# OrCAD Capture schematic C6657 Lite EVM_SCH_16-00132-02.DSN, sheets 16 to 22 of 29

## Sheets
16 PAGE16 : DSP_EMIF & JTAG: size C; title: DSP EMIF & JTAG
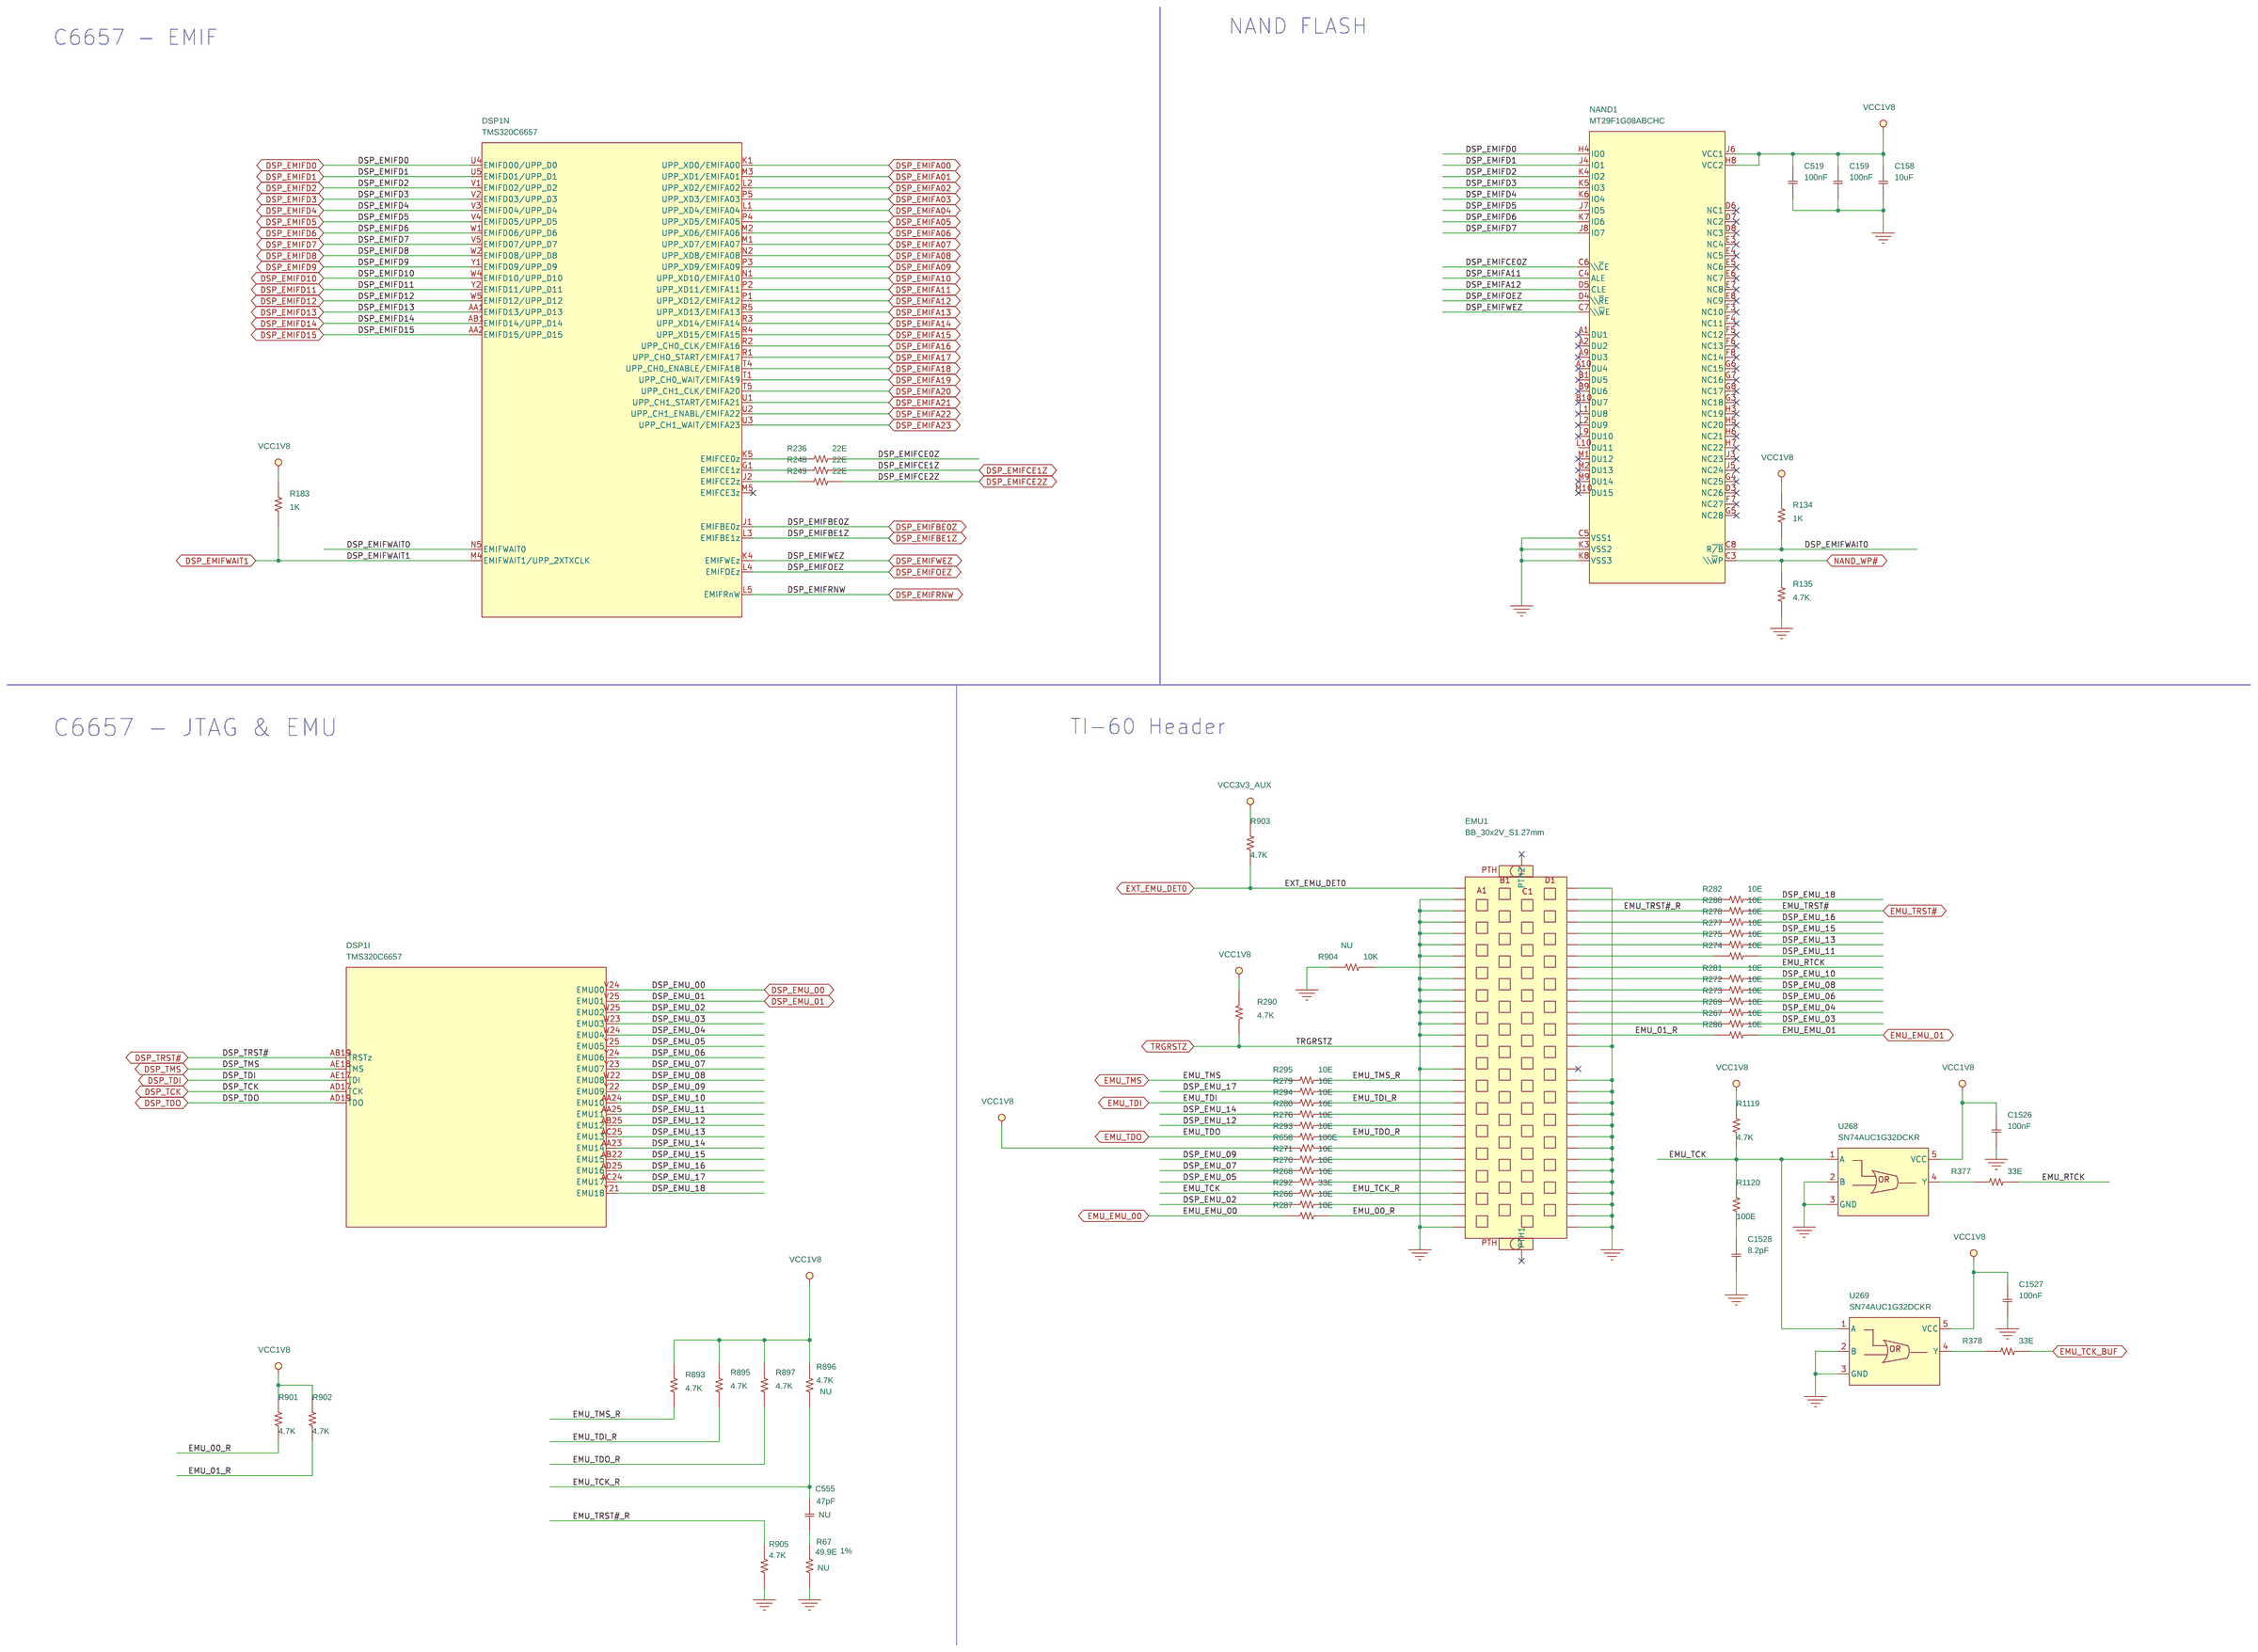
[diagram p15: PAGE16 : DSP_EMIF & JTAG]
17 PAGE29 : REVISON HISTORY: size C; title: REVISION HISTORY
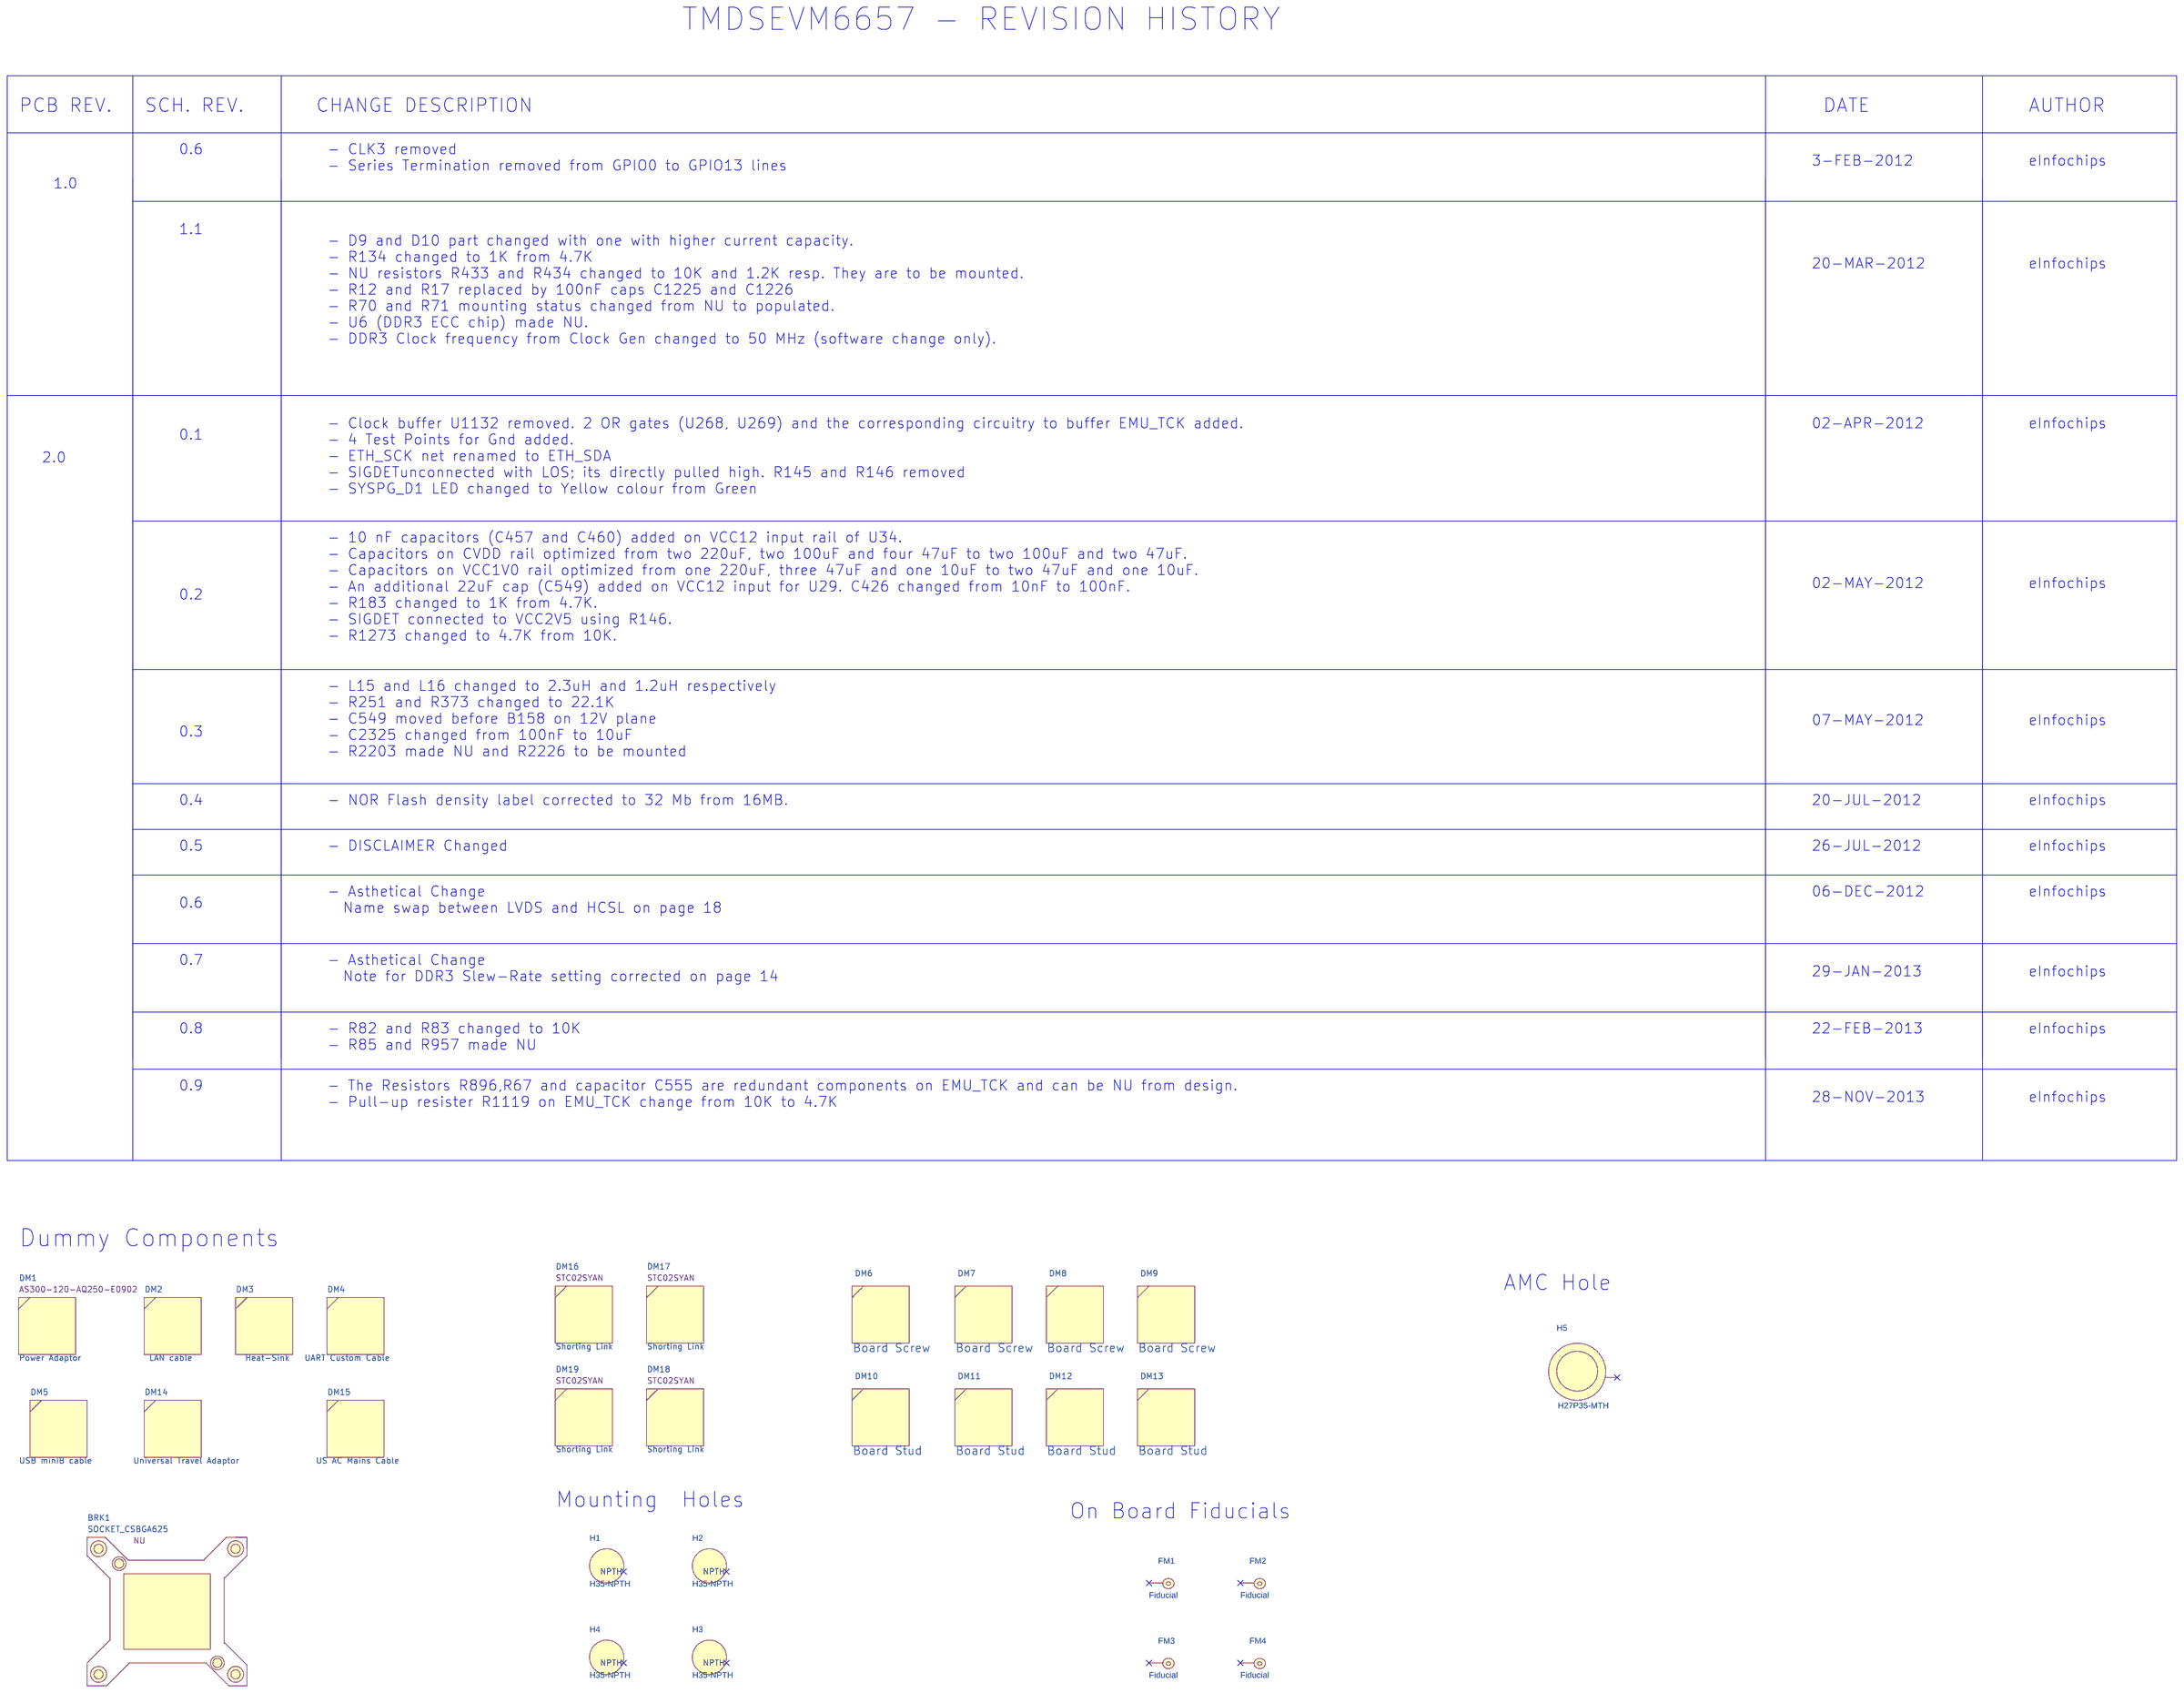
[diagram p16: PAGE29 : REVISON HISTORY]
18 PAGE05 : POWER CONSUMPTION: title: POWER CONSUMPTION
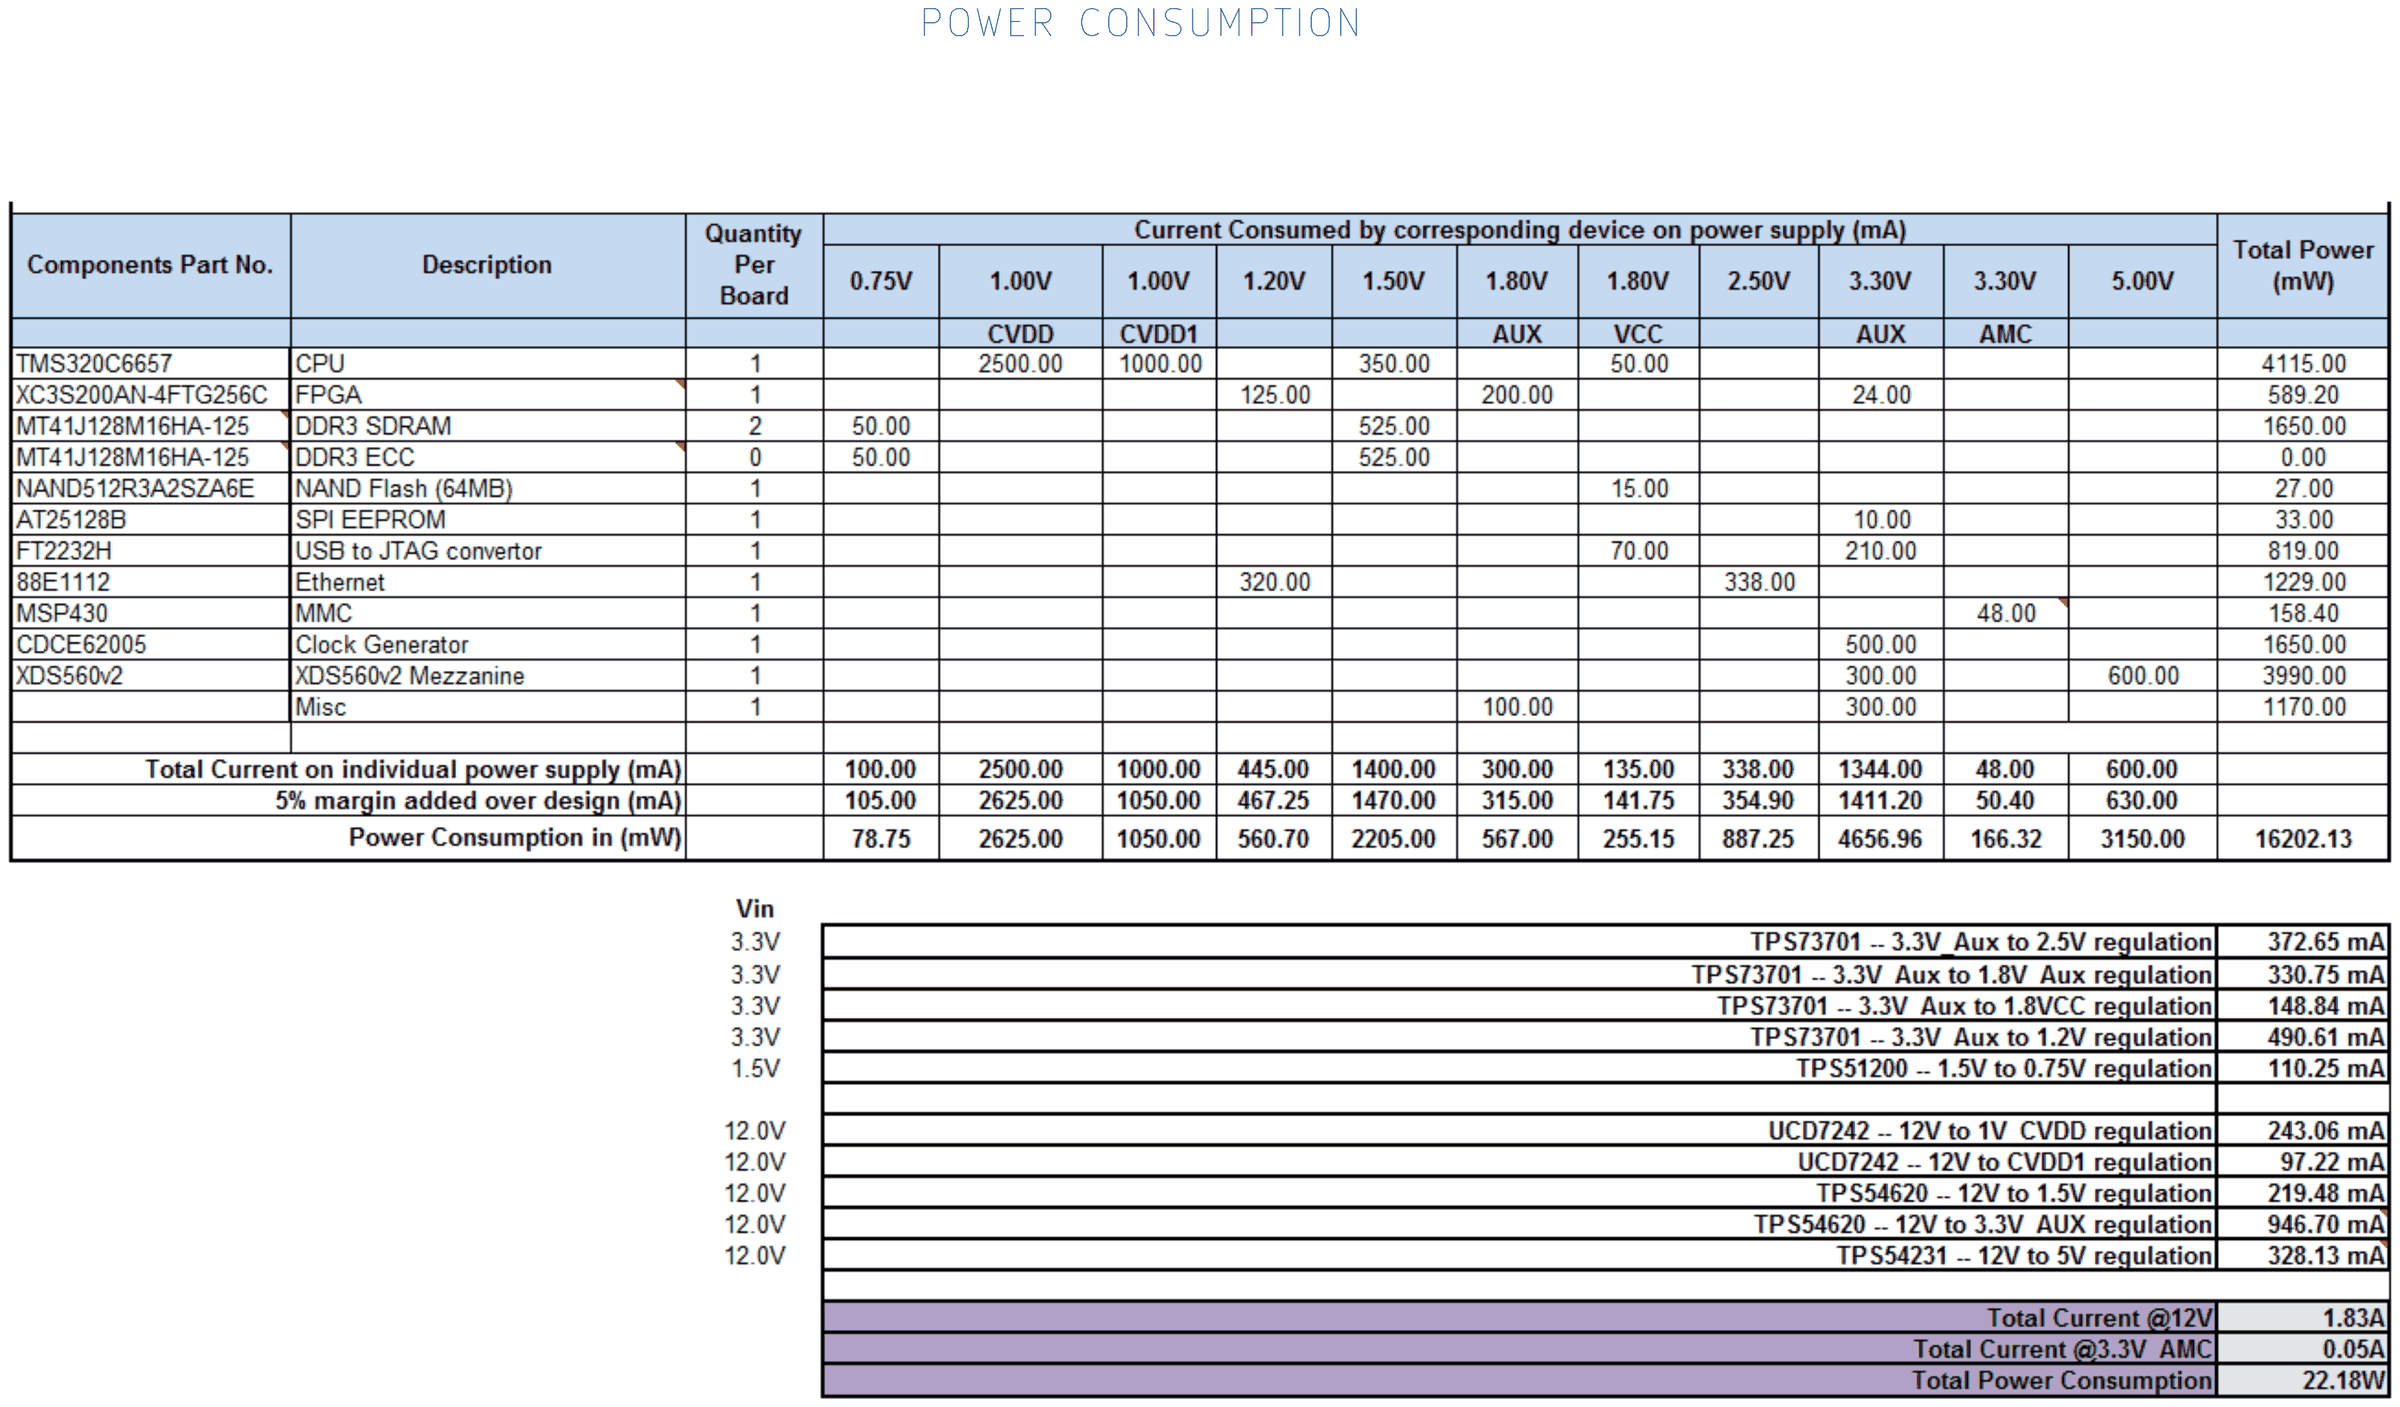
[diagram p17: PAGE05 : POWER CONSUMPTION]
19 PAGE21 : GIGABIT ETHERNET: size C; title: GIGABIT ETHERNET
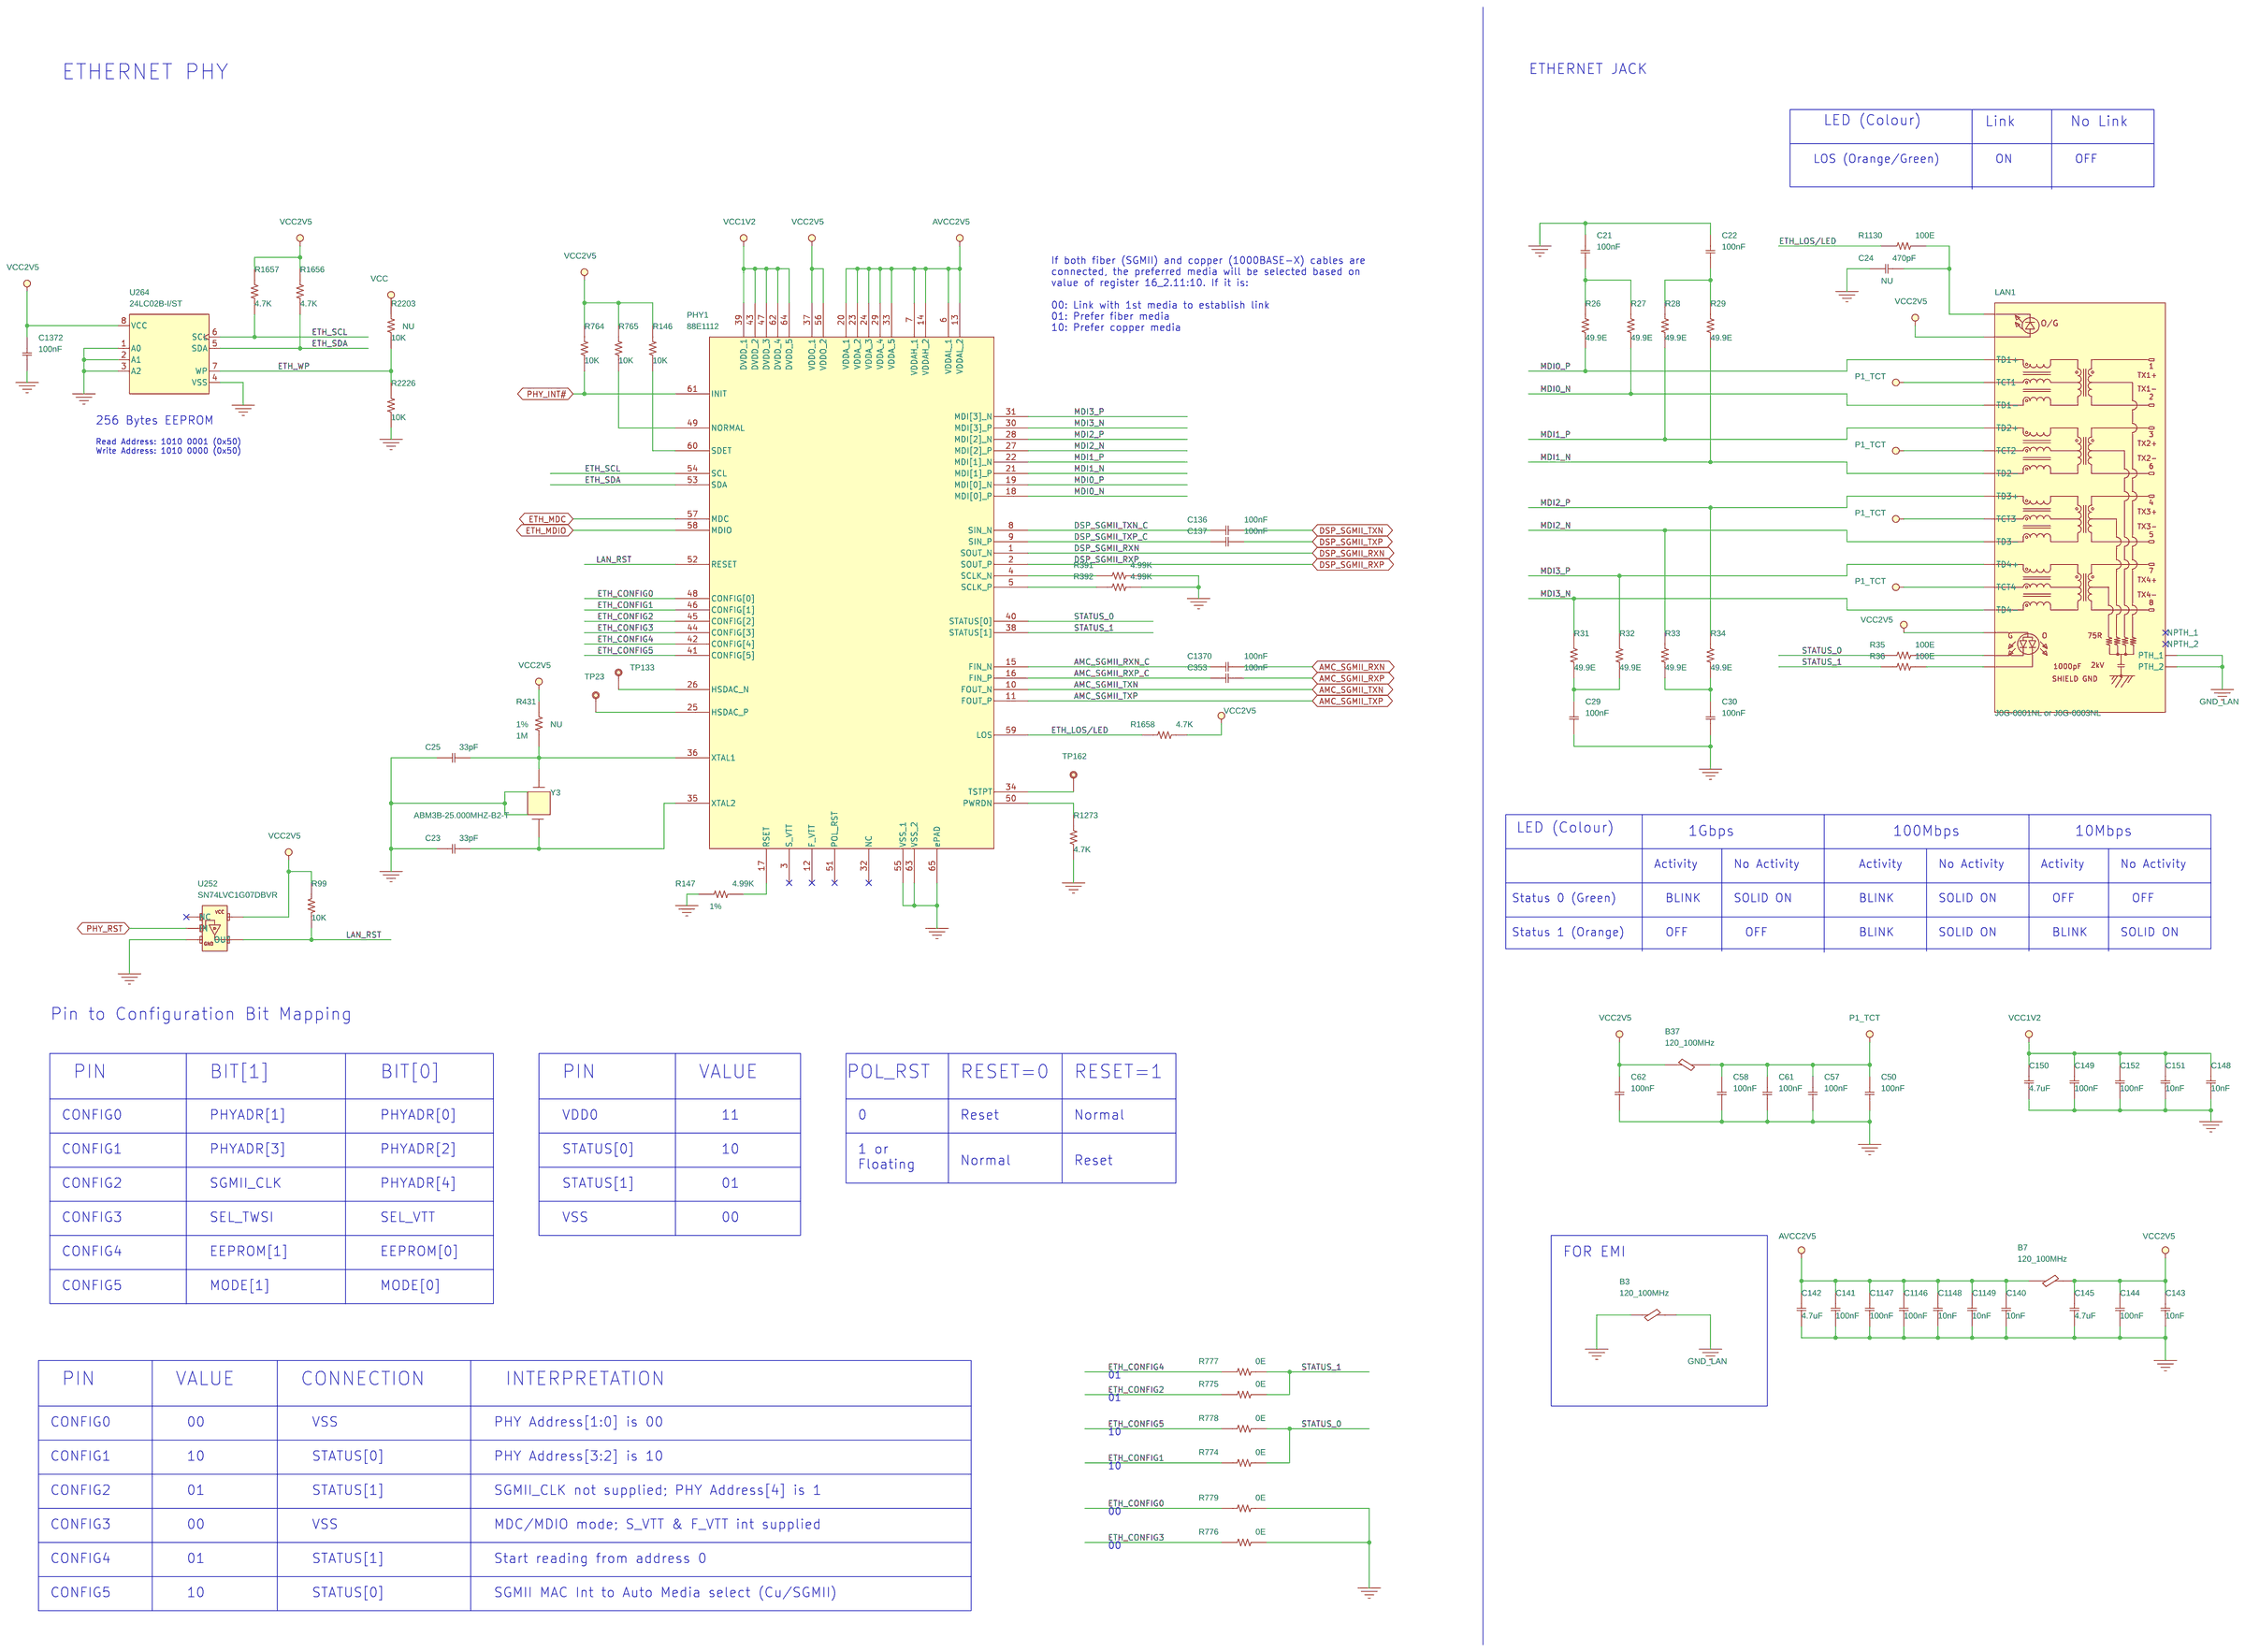
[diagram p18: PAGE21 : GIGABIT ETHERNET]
20 PAGE19 : CLOCK_GENERATION: size C; title: CLOCK GENRATION
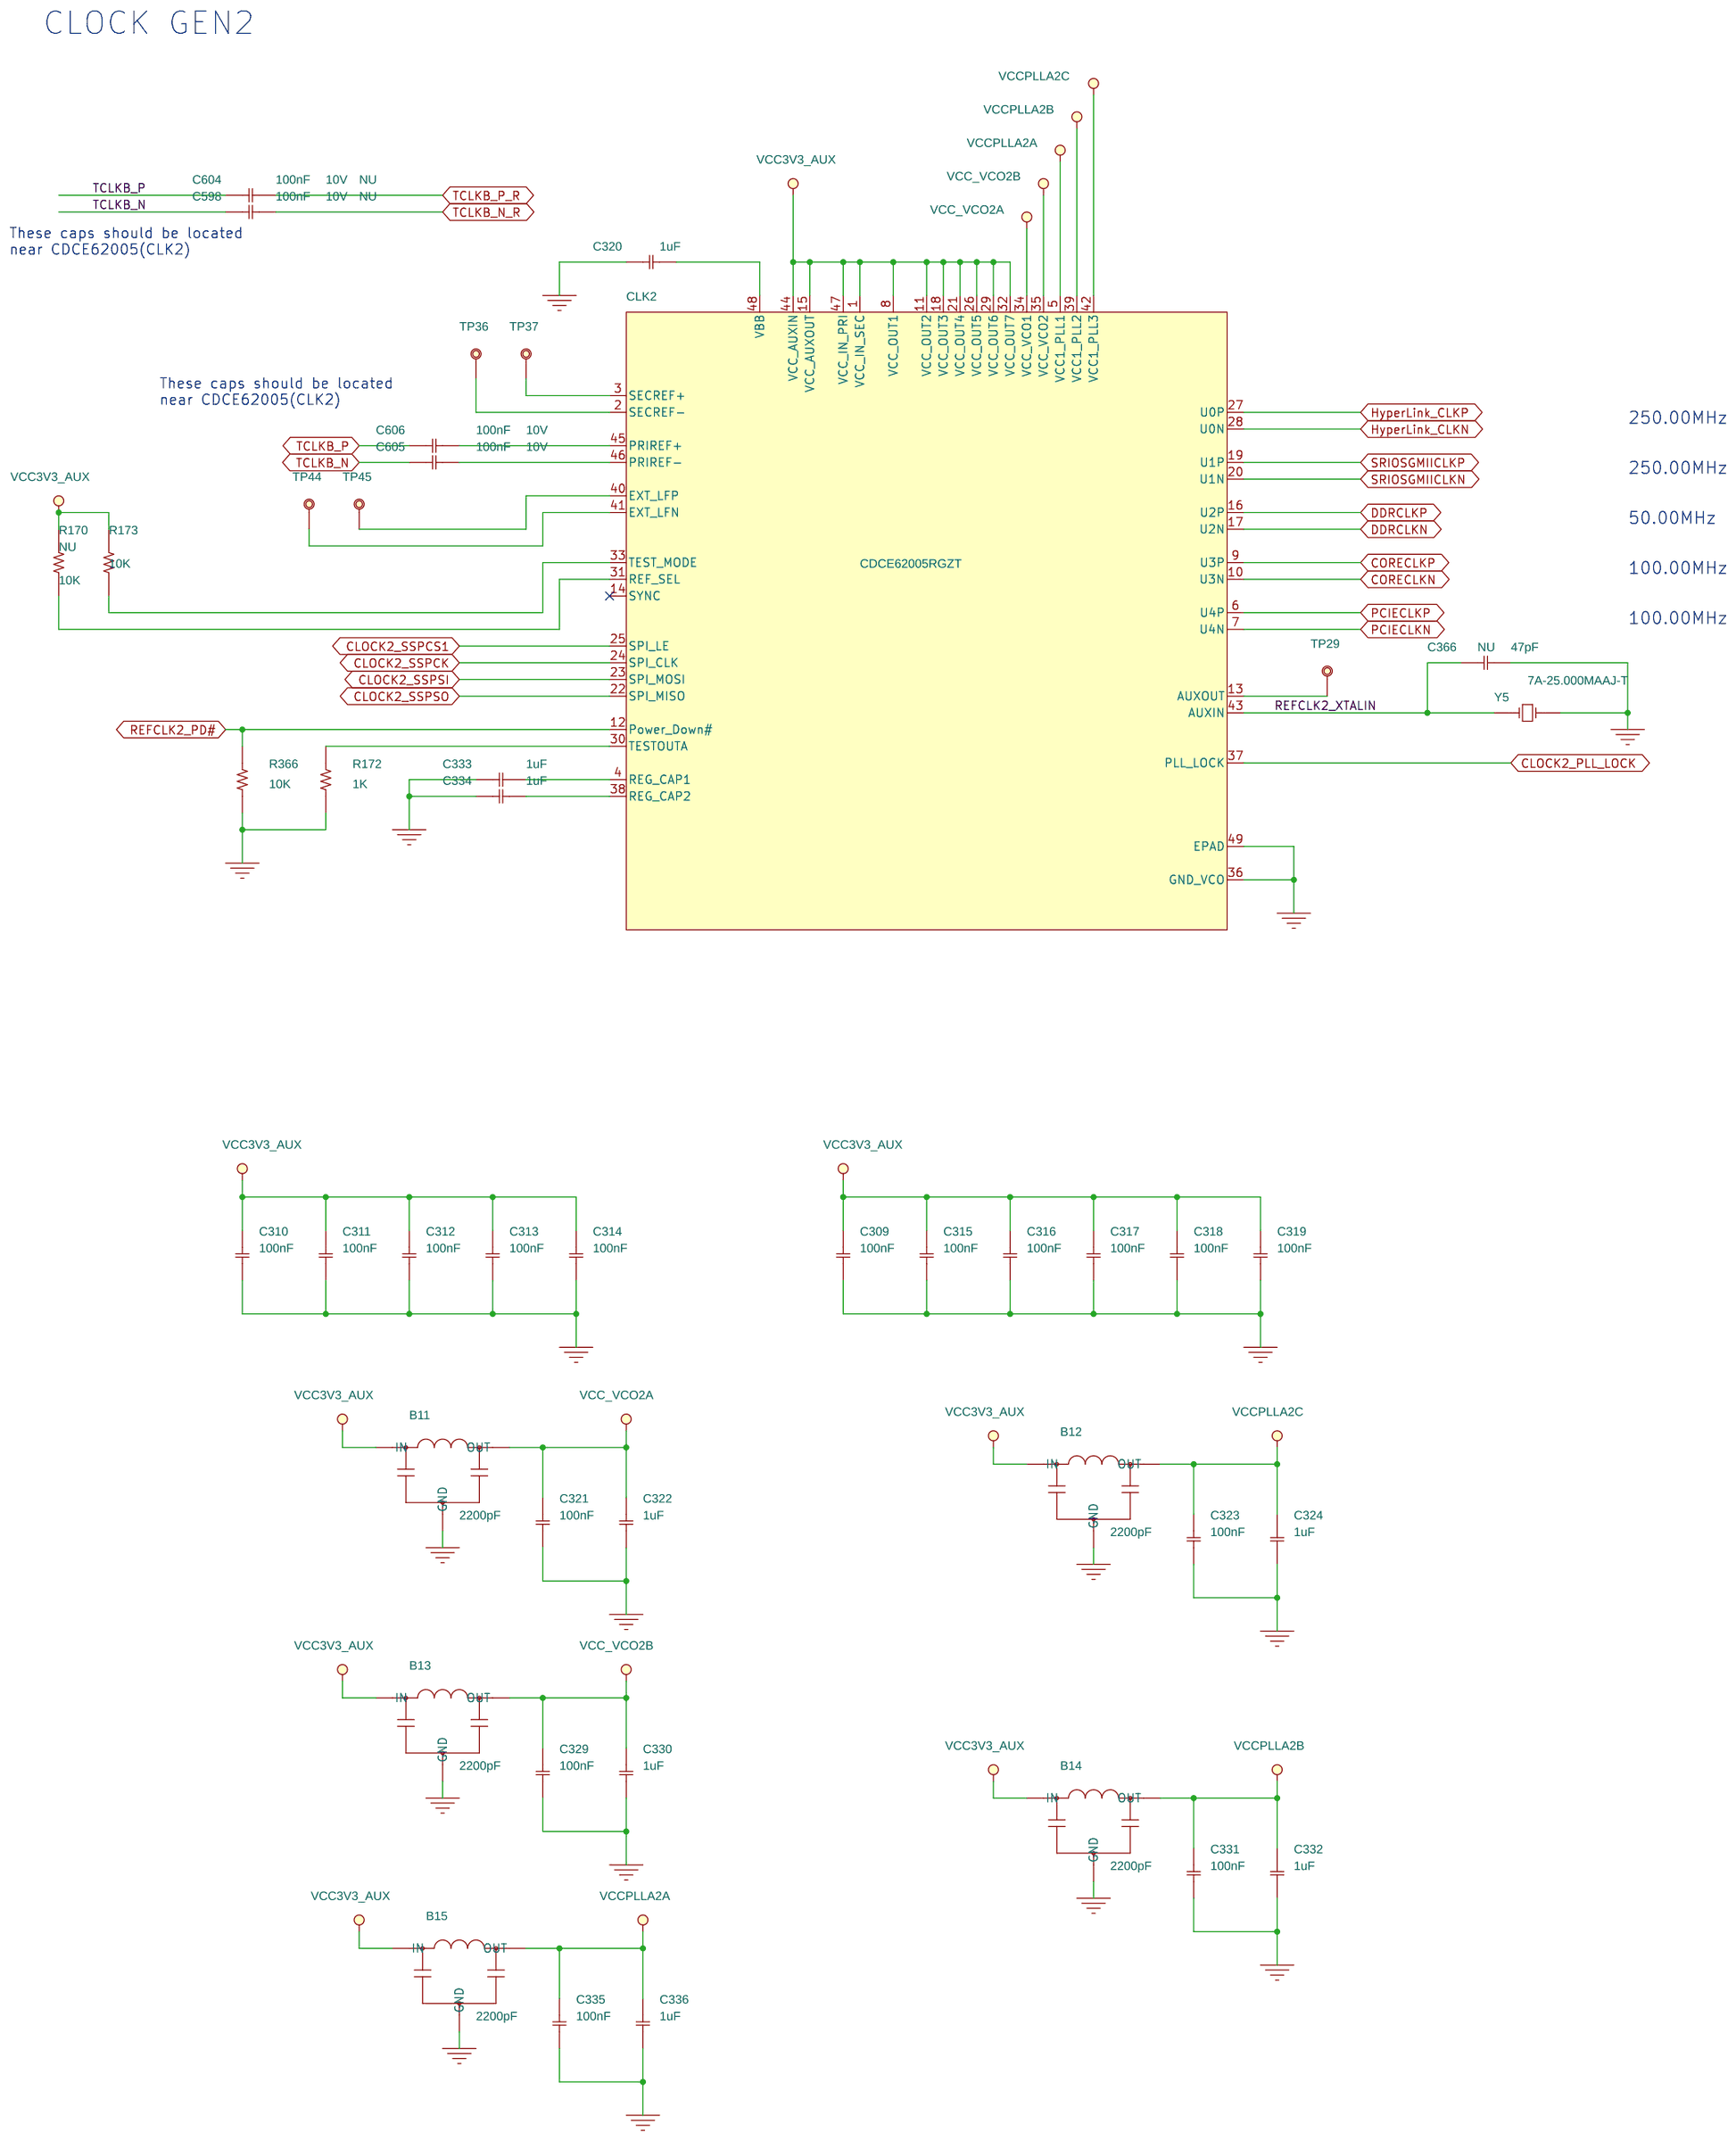
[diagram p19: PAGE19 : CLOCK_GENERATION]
21 PAGE02 : TABLE OF CONTENTS: title: TABLE OF CONTENTS
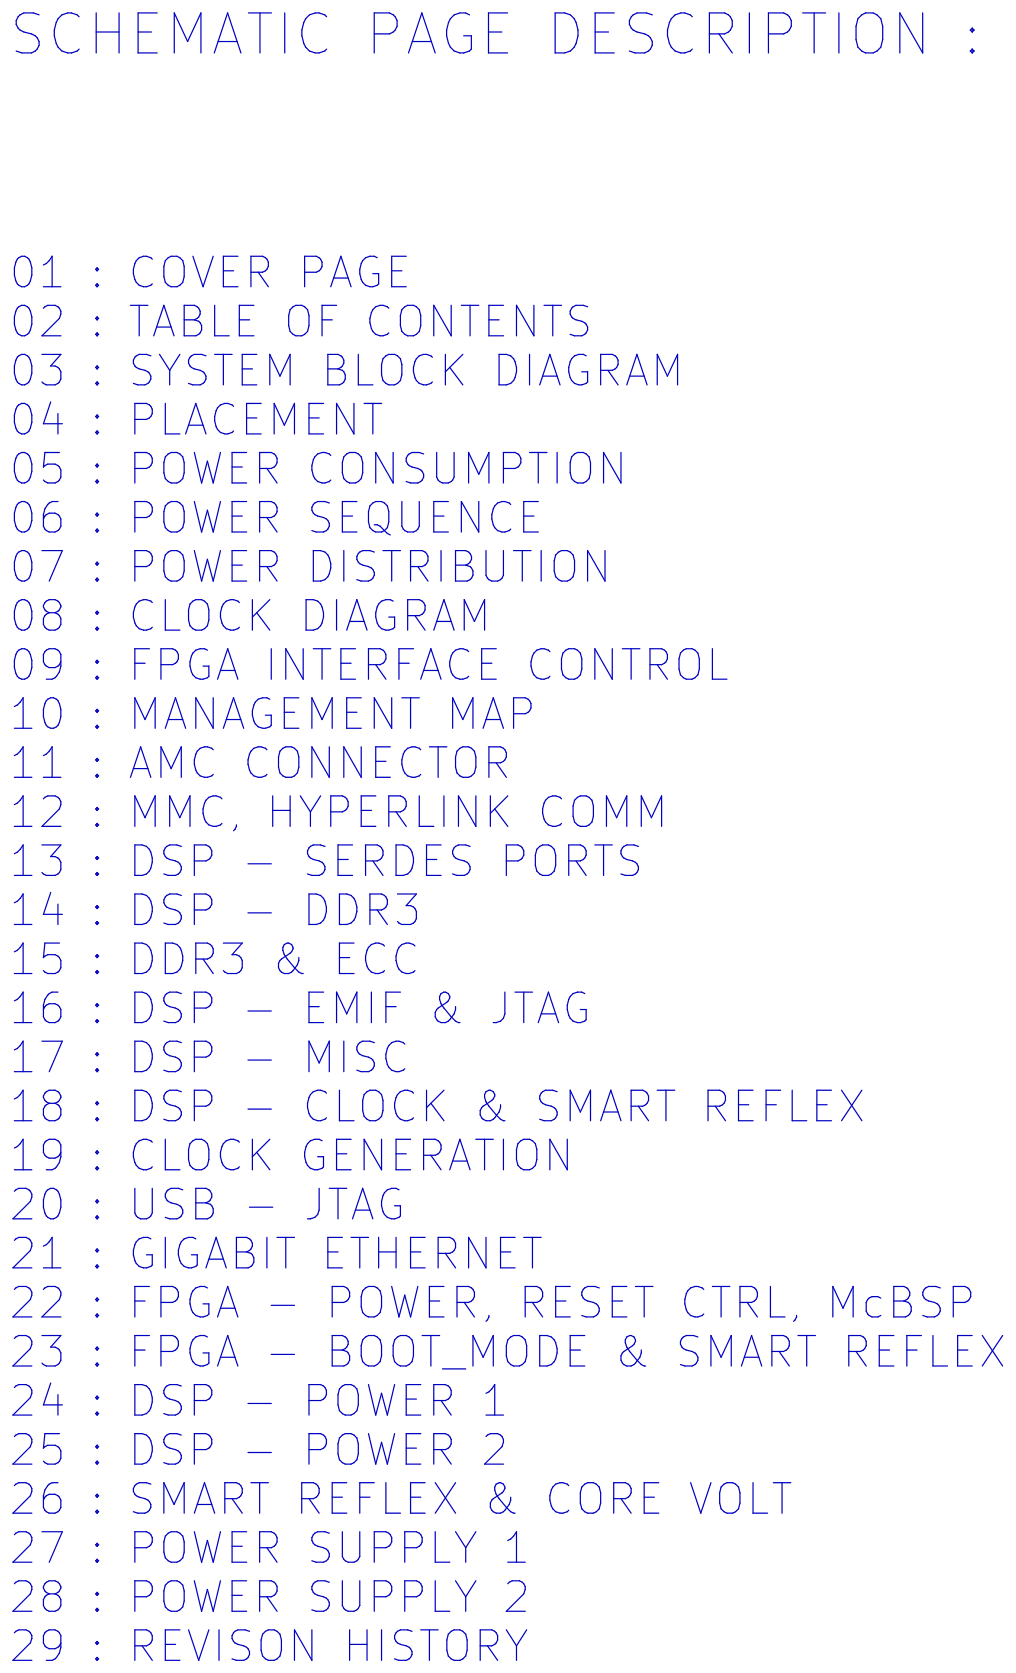
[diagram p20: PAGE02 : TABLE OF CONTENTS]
22 PAGE03 : SYSTEM BLOCK DIAGRAM: title: BLOCK DIAGRAM
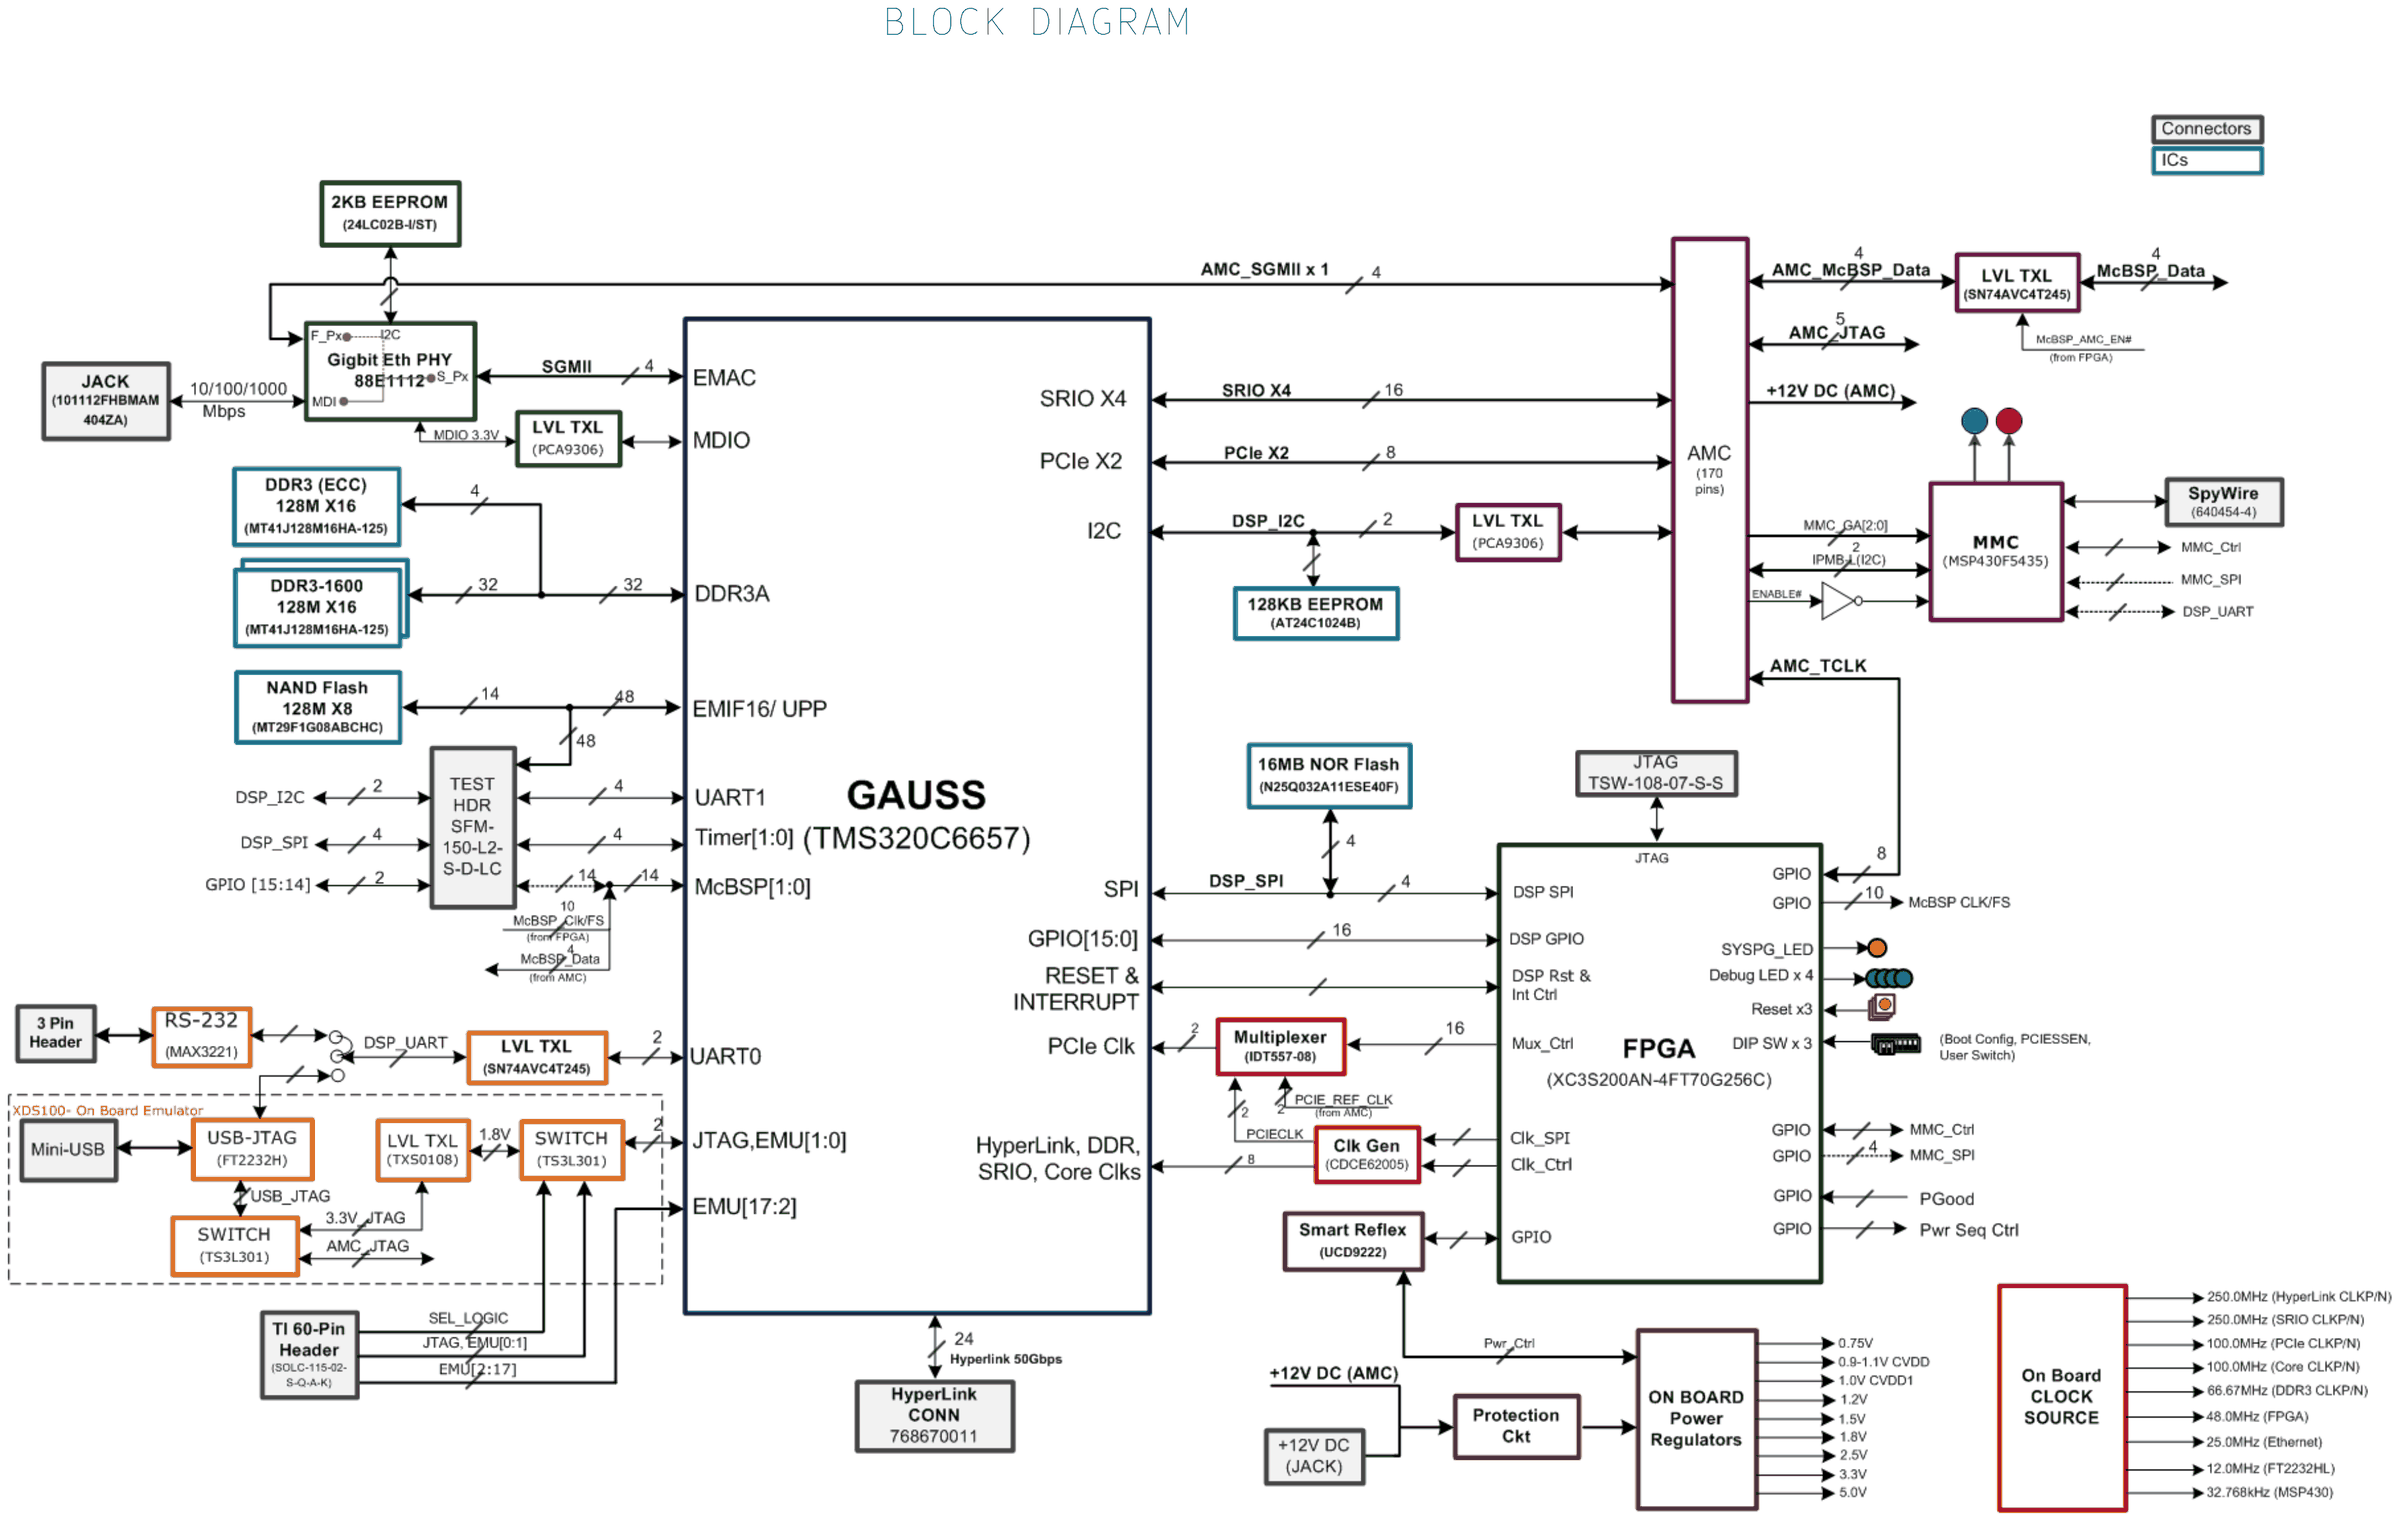
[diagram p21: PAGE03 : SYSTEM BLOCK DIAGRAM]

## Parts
sheet PAGE16 : DSP_EMIF & JTAG
C158  10uF  [C0603]
C159  100nF  [C0402]
C519  100nF  [C0402]
C555  47pF  [C0402]
C1526  100nF  [C0402]
C1527  100nF  [C0402]
C1528  8.2pF  [C0402]
EMU1  BB_30x2V_S1.27mm  [BB_30x2P_50_770x250_2HOLD]
NAND1  MT29F1G08ABCHC  [VFBGA80P_10P5X15_63_EINF]
R67  49.9E  [R0402]
R134  1K  [R0402]
R135  4.7K  [R0402]
R183  1K  [R0402]
R236  22E  [R0402]
R248  22E  [R0402]
R249  22E  [R0402]
R266  10E  [R0402]
R267  10E  [R0402]
R268  10E  [R0402]
R269  10E  [R0402]
R270  10E  [R0402]
R271  10E  [R0402]
R272  10E  [R0402]
R273  10E  [R0402]
R274  10E  [R0402]
R275  10E  [R0402]
R276  10E  [R0402]
R277  10E  [R0402]
R278  10E  [R0402]
R279  10E  [R0402]
R280  10E  [R0402]
R281  10E  [R0402]
R282  10E  [R0402]
R286  10E  [R0402]
R287  10E  [R0402]
R288  10E  [R0402]
R290  4.7K  [R0402]
R292  33E  [R0402]
R293  10E  [R0402]
R294  10E  [R0402]
R295  10E  [R0402]
R377  33E  [R0402]
R378  33E  [R0402]
R658  100E  [R0402]
R893  4.7K  [R0402]
R895  4.7K  [R0402]
R896  4.7K  [R0402]
R897  4.7K  [R0402]
R901  4.7K  [R0402]
R902  4.7K  [R0402]
R903  4.7K  [R0402]
R904  10K  [R0402]
R905  4.7K  [R0402]
R1119  4.7K  [R0402]
R1120  100E  [R0402]
U268  SN74AUC1G32DCKR  [SC70_5P]
U269  SN74AUC1G32DCKR  [SC70_5P]
sheet PAGE19 : CLOCK_GENERATION
B11  2200pF  [L_3P_70_63X35]
B12  2200pF  [L_3P_70_63X35]
B13  2200pF  [L_3P_70_63X35]
B14  2200pF  [L_3P_70_63X35]
B15  2200pF  [L_3P_70_63X35]
C309  100nF  [C0402]
C310  100nF  [C0402]
C311  100nF  [C0402]
C312  100nF  [C0402]
C313  100nF  [C0402]
C314  100nF  [C0402]
C315  100nF  [C0402]
C316  100nF  [C0402]
C317  100nF  [C0402]
C318  100nF  [C0402]
C319  100nF  [C0402]
C320  1uF  [C0402]
C321  100nF  [C0402]
C322  1uF  [C0402]
C323  100nF  [C0402]
C324  1uF  [C0402]
C329  100nF  [C0402]
C330  1uF  [C0402]
C331  100nF  [C0402]
C332  1uF  [C0402]
C333  1uF  [C0402]
C334  1uF  [C0402]
C335  100nF  [C0402]
C336  1uF  [C0402]
C366  47pF  [C0402]
C598  100nF  [C0402]
C604  100nF  [C0402]
C605  100nF  [C0402]
C606  100nF  [C0402]
CLK2  CDCE62005RGZT  [QFN_48P_20_276X276_TP220V25]
R170  10K  [R0402]
R172  1K  [R0402]
R173  10K  [R0402]
R366  10K  [R0402]
TP29  Test Point  [TP-S40]
TP36  Test Point  [TP-S40]
TP37  Test Point  [TP-S40]
TP44  Test Point  [TP-S40]
TP45  Test Point  [TP-S40]
Y5  7A-25.000MAAJ-T  [XTAL_ABM3]
sheet PAGE21 : GIGABIT ETHERNET
B3  120_100MHz  [L0402]
B7  120_100MHz  [L0402]
B37  120_100MHz  [L0402]
C21  100nF  [C0402]
C22  100nF  [C0402]
C23  33pF  [C0402]
C24  470pF  [C0402]
C25  33pF  [C0402]
C29  100nF  [C0402]
C30  100nF  [C0402]
C50  100nF  [C0402]
C57  100nF  [C0402]
C58  100nF  [C0402]
C61  100nF  [C0402]
C62  100nF  [C0402]
C136  100nF  [C0402]
C137  100nF  [C0402]
C140  10nF  [C0402]
C141  100nF  [C0402]
C142  4.7uF  [C0603]
C143  10nF  [C0402]
C144  100nF  [C0402]
C145  4.7uF  [C0603]
C148  10nF  [C0402]
C149  100nF  [C0402]
C150  4.7uF  [C0603]
C151  10nF  [C0402]
C152  100nF  [C0402]
C353  100nF  [C0402]
C1146  100nF  [C0402]
C1147  100nF  [C0402]
C1148  10nF  [C0402]
C1149  10nF  [C0402]
C1370  100nF  [C0402]
C1372  100nF  [C0402]
LAN1  J0G-0001NL or J0G-0003NL  [RJ45_17P_101112FHBMAM404ZA]
PHY1  88E1112  [qfn50p900x900_64_pwp_a_EINF]
R26  49.9E  [R0402]
R27  49.9E  [R0402]
R28  49.9E  [R0402]
R29  49.9E  [R0402]
R31  49.9E  [R0402]
R32  49.9E  [R0402]
R33  49.9E  [R0402]
R34  49.9E  [R0402]
R35  100E  [R0402]
R36  100E  [R0402]
R99  10K  [R0402]
R146  10K  [R0402]
R147  4.99K  [R0402]
R391  4.99K  [R0402]
R392  4.99K  [R0402]
R431  1M  [R0402]
R764  10K  [R0402]
R765  10K  [R0402]
R774  0E  [R0402]
R775  0E  [R0402]
R776  0E  [R0402]
R777  0E  [R0402]
R778  0E  [R0402]
R779  0E  [R0402]
R1130  100E  [R0402]
R1273  4.7K  [R0402]
R1656  4.7K  [R0402]
R1657  4.7K  [R0402]
R1658  4.7K  [R0402]
R2203  10K  [R0402]
R2226  10K  [R0402]
TP23  Test Point  [TP-S40]
TP133  Test Point  [TP-S40]
TP162  Test Point  [TP-S40]
U252  SN74LVC1G07DBVR  [SOT-23_5P]
U264  24LC02B-I/ST  [TSSOP65P640_8]
Y3  ABM3B-25.000MHZ-B2-T  [XTAL_ABM3B]
sheet PAGE25 : DSP_POWER 2
DSP1  TMS320C6657  [BGA80P_38X38_625_SKT_EINF]  (sections A,B,C,D,E,F,G,H,I,J,K,L,M,N,O,P,Q,R,S,T)
sheet PAGE29 : REVISON HISTORY
BRK1  SOCKET_CSBGA625  [NA]
DM1  Power Adaptor  [NA]
DM2  LAN cable  [NA]
DM3  Heat-Sink  [HEATSINK_MBA23002-22P]
DM4  UART Custom Cable  [NA]
DM5  USB miniB cable  [NA]
DM6  Board Screw  [-- NA --]
DM7  Board Screw  [-- NA --]
DM8  Board Screw  [-- NA --]
DM9  Board Screw  [-- NA --]
DM10  Board Stud  [NA]
DM11  Board Stud  [NA]
DM12  Board Stud  [NA]
DM13  Board Stud  [NA]
DM14  Universal Travel Adaptor  [NA]
DM15  US AC Mains Cable  [-- NA --]
DM16  Shorting Link  [-- NA --]
DM17  Shorting Link  [-- NA --]
DM18  Shorting Link  [-- NA --]
DM19  Shorting Link  [-- NA --]
FM1  Fiducial  [Fiducial]
FM2  Fiducial  [Fiducial]
FM3  Fiducial  [Fiducial]
FM4  Fiducial  [Fiducial]
H1  H35-NPTH  [H35-NPTH]
H2  H35-NPTH  [H35-NPTH]
H3  H35-NPTH  [H35-NPTH]
H4  H35-NPTH  [H35-NPTH]
H5  H27P35-MTH  [H27P35-MTH]

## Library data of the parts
C158 = 11_C_0: CAP CER 10UF 6.3V 20% X5R 0603; Manufacture Part Number: C1608X5R0J106MT||2255 206 13776||CC0603MRX5R5BB106; Mfg: Murata; Mfg Part#: GRM188R60J106ME47D; Oper. Temp. Range: -55C to 85C; Package: 0603; ProcessType: SMT; RoHS: Yes; Tolerance: 20%; Vendor: DigiKey; Vendor Part#: 490-3896-1-ND; eI Part#: 03_00058_03
C21 C22 C29 C30 C50 C57 C58 C61 C62 C136 C137 C141 C144 C149 C152 C159 C309-C319 C321 C323 C329 C331 C335 C353 C519 C1146 C1147 C1370 C1372 C1526 C1527 = 11_C_0: CAP CER 0.1UF 10V 10% X5R 0402; Alt Mfg: Murata; Alt Mfg Part#: GRM155R61A104KA01D; Manufacture Part Number: 2238 787 15649||CC0402KRX7R7BB104; Mfg: Yageo; Mfg Part#: CC0402KRX5R6BB104; Oper. Temp. Range: -55C to 85C; Package: 0402; ProcessType: SMT; RoHS: Yes; Tolerance: 10%; Vendor: DigiKey; Vendor Part#: 311-1336-1-ND; eI Part#: 03_00021_02
C555 = 11_C_0: CAP CER 47PF 50V 5% NP0 0402; Manufacture Part Number: 223886915479; Mfg: Yageo; Mfg Part#: CC0402JRNPO9BN470; Mounting Status: NU; Oper. Temp. Range: -55C to 85C; Package: 0402; ProcessType: SMT; RoHS: Yes; Tolerance: 5%; Vendor: DigiKey; Vendor Part#: 311-1021-1-ND; eI Part#: 03_00046_04
C1528 = 11_C_0: CAP CER 8.2PF 50V NP0 0402; Mfg: Taiyo Yuden; Mfg Part#: UMK105CG8R2DV-F; Oper. Temp. Range: -55C to 125C; Package: 0402; ProcessType: SMT; RoHS: Yes; Tolerance: +/-0.5pF; Vendor: DigiKey; Vendor Part#: 587-1946-1-ND; eI Part#: 03_00306_02
EMU1 = 1654_BB_30X2P_SOLC-115-02_0: CONN  DENSITY SOCKET  60 PIN .25''; Manufacture Part Number: SOLC-115-02-S-Q-LC; Mfg: Samtec; Mfg Part#: SOLC-115-02-S-Q-A-K; Package: BB30x2P-S1.27; ProcessType: SMT; RoHS: Yes; Vendor: Samtec; Vendor Part#: SOLC-115-02-S-Q-A-K; eI Part#: 09_00146_01
NAND1 = NAND512R3A2DZA6E_2: IC NAND Flash 1GBIT 63VFBGA; Alt Mfg: Micron; Alt Mfg Part#: MT29F1G08ABBDAH4; Mfg: Micron; Package: 63-VFBGA; Remark: Main part supports 1 bit ECC and alt part supports 4 bit ECC. FPP supports both HC and H4 pkg; RoHS: Yes; Vendor: DigiKey; Vendor Part#: MT29F1G08ABCHC:C TR-ND; eI Part#: 01_00849_01
R67 = 10_R_0: RES 49.9 OHM 1/10W 1% 0402 SMD; Alt Mfg: Yageo; Alt Mfg Part#: RC0402FR-0749R9L; Manufacture Part Number: 0402WGF499JTCE||232270674999L||RC0402FR-0749R9||RM04FTN49R9; Mfg: Panasonic - ECG; Mfg Part#: ERJ-2RKF49R9X; Mounting Status: NU; Oper. Temp. Range: -55C to 125C; Package: 0402; ProcessType: SMT; RoHS: Yes; Tolerance: 1%; Vendor: DigiKey; Vendor Part#: P49.9LCT-ND; eI Part#: 02_00025_01
R134 R172 R183 = 10_R_0: RES 1.00K OHM 1/10W 1% 0402 SMD; Alt Mfg: Yageo; Alt Mfg Part#: RC0402FR-071KL; MOUNTED: <MOUNTED>; Manufacture Part Number: 0402WGF1001TCE||RM04FTN1001; Mfg: Panasonic - ECG; Mfg Part#: ERJ-2RKF1001X; Oper. Temp. Range: -55C to 125C; Package: 0402; ProcessType: SMT; RoHS: Yes; Tolerance: 1%; Vendor: DigiKey; Vendor Part#: P1.00KLCT-ND; eI Part#: 02_00045_01
R135 R290 R893 R895 R897 R905 = 10_R_0: RES 4.7K OHM 1/10W 5% 0402 SMD; Alt Mfg: Yageo; Alt Mfg Part#: RC0402JR-074K7L; Manufacture Part Number: 0402WGJ0472TCE||RC0402JR-074K7L||RM04JTN472; Mfg: Panasonic - ECG; Mfg Part#: ERJ-2GEJ472X; Oper. Temp. Range: -55C to 125C; Package: 0402; ProcessType: SMT; Remark: Alt part is 1/16W; RoHS: Yes; Tolerance: 5%; Vendor: DigiKey; Vendor Part#: P4.7KJCT-ND; eI Part#: 02_00023_01
R236 R248 R249 = 10_R_0: RES 22 OHM 1/10W 5% 0402 SMD; Mfg: Panasonic - ECG; Mfg Part#: ERJ-2GEJ220X; Oper. Temp. Range: -55C to 125C; Package: 0402; ProcessType: SMT; Remark: Alt part is 1/16W; RoHS: Yes; Tolerance: 5%; Vendor: DigiKey; Vendor Part#: P22JCT-ND; eI Part#: 02_00233_01
R266-R282 R286-R288 R293-R295 = 10_R_0: RES 10.0 OHM 1/10W 1% 0402 SMD; Manufacture Part Number: 0402WGJ0100TCE||RC0402JR-0710RL||RM04JTN100; Mfg: Panasonic - ECG; Mfg Part#: ERJ-2RKF10R0X; Oper. Temp. Range: -55C to 125C; Package: 0402; ProcessType: SMT; RoHS: Yes; Tolerance: 1%; Vendor: DigiKey; Vendor Part#: P10.0LCT-ND; eI Part#: 02_00060_01
R292 R377 R378 = 10_R_0: RES 33.0 OHM 1/10W 1% 0402 SMD; Alt Mfg: Yageo; Alt Mfg Part#: RC0402FR-0733RL; Manufacture Part Number: 0402WGJ0330TCE||232270570339L||RC0402JR-0733RL||RM04JTN330; Mfg: Panasonic - ECG; Mfg Part#: ERJ-2RKF33R0X; Oper. Temp. Range: -55C to 125C; Package: 0402; ProcessType: SMT; Remark: Alt part is 1/16W; RoHS: Yes; Tolerance: 1%; Vendor: DigiKey; Vendor Part#: P33.0LCT-ND; eI Part#: 02_00018_05
R658 = 10_R_0: RES 100 OHM 1/10W 1% 0402 SMD; MOUNTED: <MOUNTED>; Manufacture Part Number: 0402WGF1000TCE||232270671001L||RM04FTN1000; Mfg: Panasonic - ECG; Mfg Part#: ERJ-2RKF1000X; Oper. Temp. Range: -55C to 125C; Package: 0402; ProcessType: SMT; RoHS: Yes; Tolerance: 1%; Vendor: DigiKey; Vendor Part#: P100LCT-ND; eI Part#: 02_00043_02
R896 = 10_R_0: RES 4.7K OHM 1/10W 5% 0402 SMD; Alt Mfg: Yageo; Alt Mfg Part#: RC0402JR-074K7L; Manufacture Part Number: 0402WGJ0472TCE||RC0402JR-074K7L||RM04JTN472; Mfg: Panasonic - ECG; Mfg Part#: ERJ-2GEJ472X; Mounting Status: NU; Oper. Temp. Range: -55C to 125C; Package: 0402; ProcessType: SMT; Remark: Alt part is 1/16W; RoHS: Yes; Tolerance: 5%; Vendor: DigiKey; Vendor Part#: P4.7KJCT-ND; eI Part#: 02_00023_01
R901-R903 R1119 = 10_R_0: RES 4.7K OHM 1/10W 5% 0402 SMD; Alt Mfg: Yageo; Alt Mfg Part#: RC0402JR-074K7L; Manufacture Part Number: RM04FTN4751; Mfg: Panasonic - ECG; Mfg Part#: ERJ-2GEJ472X; Oper. Temp. Range: -55C to 125C; Package: 0402; ProcessType: SMT; Remark: Alt part is 1/16W; RoHS: Yes; Tolerance: 5%; Vendor: DigiKey; Vendor Part#: P4.7KJCT-ND; eI Part#: 02_00023_01
R170 R904 R2203 = 10_R_0: RES 10.0K OHM 1/10W 1% 0402 SMD; Alt Mfg: Yageo; Alt Mfg Part#: RC0402FR-0710KL; Manufacture Part Number: 0402WGF1002TCE||RM04FTN1002; Mfg: Panasonic - ECG; Mfg Part#: ERJ-2RKF1002X; Mounting Status: NU; Mounting_Status: NU; Oper. Temp. Range: -55C ~ 125C; Package: 0402; ProcessType: SMT; Remark: Alt part is 1/16W; RoHS: Yes; Tolerance: 1%; Vendor: DigiKey; Vendor Part#: P10.0KLCT-ND; eI Part#: 02_00027_01
R35 R36 R1120 R1130 = 10_R_0: RES 100 OHM 1/10W 1% 0402 SMD; Manufacture Part Number: 0402WGF1000TCE||232270671001L||RM04FTN1000; Mfg: Panasonic - ECG; Mfg Part#: ERJ-2RKF1000X; Oper. Temp. Range: -55C to 125C; Package: 0402; ProcessType: SMT; RoHS: Yes; Tolerance: 1%; Vendor: DigiKey; Vendor Part#: P100LCT-ND; eI Part#: 02_00043_02
U268 U269 = SN74AUC1G32DCKR: IC GATE 2-IN POS-OR SGL SC-70-5; Mfg: Texas Instruments; Package: 6-TSSOP; RoHS: Yes; Vendor: DigiKey; Vendor Part#: 296-12656-1-ND; eI Part#: 01_00879_01
B11-B15 = 1212_FILTER_NFW31SP106X1E4L_0: FILTER LC HIGH FREQ 2200PF 0603; Manufacture Part Number: NFM18CC222R1C3D; Mfg: Murata; Mfg Part#: NFM18CC222R1C3D; Oper. Temp. Range: -55C to 125C; Package: 0603; ProcessType: SMT; RoHS: Yes; Tolerance: 20%; Vendor: DigiKey; Vendor Part#: NFM18CC222R1C3D-ND; eI Part#: 04_00026_01
C320 C322 C324 C330 C332-C334 C336 = 11_C_0: CAP CER 1.0UF 16V X5R 0402; Manufacture Part Number: C1005X5R0J105KT||C0402B105K007T; Mfg: TDK Corp; Mfg Part#: C1005X5R1C105K; Oper. Temp. Range: -55C to 85C; Package: 0402; ProcessType: SMT; RoHS: Yes; Tolerance: 10%; Vendor: DigiKey; Vendor Part#: 445-4978-1-ND; eI Part#: 03_00264_01
C366 = 11_C_0: CAP CER 47PF 50V 5% NP0 0402; Manufacture Part Number: 223886915479; Mfg: Yageo; Mfg Part#: CC0402JRNPO9BN470; Mounting Status: NU; Mounting_Status: NU; Oper. Temp. Range: -55C to 85C; Package: 0402; ProcessType: SMT; RoHS: Yes; Tolerance: 5%; Vendor: DigiKey; Vendor Part#: 311-1021-1-ND; eI Part#: 03_00046_04
C598 C604 = 11_C_0: CAP CER 0.1UF 10V 10% X5R 0402; Alt Mfg: Murata; Alt Mfg Part#: GRM155R61A104KA01D; Manufacture Part Number: 2238 787 15649||CC0402KRX7R7BB104; Mfg: Yageo; Mfg Part#: CC0402KRX5R6BB104; Mounting Status: NU; Mounting_Status: NU; Oper. Temp. Range: -55C to 85C; Package: 0402; ProcessType: SMT; RoHS: Yes; Tolerance: 10%; Vendor: DigiKey; Vendor Part#: 311-1336-1-ND; Voltage: 10V; eI Part#: 03_00021_02
C605 C606 = 11_C_0: CAP CER 0.1UF 10V 10% X5R 0402; Alt Mfg: Murata; Alt Mfg Part#: GRM155R61A104KA01D; Manufacture Part Number: 2238 787 15649||CC0402KRX7R7BB104; Mfg: Yageo; Mfg Part#: CC0402KRX5R6BB104; Oper. Temp. Range: -55C to 85C; Package: 0402; ProcessType: SMT; RoHS: Yes; Tolerance: 10%; Vendor: DigiKey; Vendor Part#: 311-1336-1-ND; Voltage: 10V; eI Part#: 03_00021_02
CLK2 = CDCE62005RGZT_0: IC CLK SYNTH/JITTER CLEANR 48QFN; Mfg: Texas Instruments; Oper. Temp. Range: -40C to 85C; Package: 48-VFQFN; RoHS: Yes; Vendor: DigiKey; Vendor Part#: 296-23947-1-ND; eI Part#: 01_00847_01
R99 R146 R173 R366 R764 R765 R2226 = 10_R_0: RES 10.0K OHM 1/10W 1% 0402 SMD; Alt Mfg: Yageo; Alt Mfg Part#: RC0402FR-0710KL; Manufacture Part Number: 0402WGF1002TCE||RM04FTN1002; Mfg: Panasonic - ECG; Mfg Part#: ERJ-2RKF1002X; Oper. Temp. Range: -55C ~ 125C; Package: 0402; ProcessType: SMT; Remark: Alt part is 1/16W; RoHS: Yes; Tolerance: 1%; Vendor: DigiKey; Vendor Part#: P10.0KLCT-ND; eI Part#: 02_00027_01
TP23 TP29 TP36 TP37 TP44 TP45 TP133 TP162 = 00_TP-S40_0: TEST PAD TP-S40; Mfg: --NA--; Mfg Part#: --NA--; Oper. Temp. Range: --NA--; Package: --NA--; ProcessType: SMT; RoHS: Yes; Vendor: --NA--; Vendor Part#: --NA--; eI Part#: --NA--
Y5 = 1231_XTAL_2P_0: CRYSTAL 25.000 MHZ 18PF SMD; Manufacture Part Number: 7A25000012; Mfg: TXC CORPORATION; Oper. Temp. Range: -20°C ~ 70°C; Package: 5.00mm x 3.20mm; ProcessType: SMT; RoHS: Yes; Tolerance: ±30ppm; Vendor: DigiKey; Vendor Part#: 887-1092-1-ND; eI Part#: 08_00127_01
B3 B7 B37 = 1212_BEAD_0: FERRITE CHIP 120 OHM 500MA 0402; Manufacture Part Number: BLM15AG121SN1D; Mfg: Murata; Mfg Part#: BLM15AG121SN1D; Oper. Temp. Range: -55C to 85C; Package: 0402; ProcessType: SMT; RoHS: Yes; Tolerance: 25%; Vendor: DigiKey; Vendor Part#: 490-1005-1-ND; eI Part#: 04_00075_01
C23 C25 = 11_C_0: CAP CER 33PF 50V 5% NPO 0402; Manufacture Part Number: 2238 787 15649||CC0402KRX7R7BB104; Mfg: Yageo; Mfg Part#: CC0402JRNPO9BN330; Oper. Temp. Range: -55C to 85C; Package: 0402; ProcessType: SMT; RoHS: Yes; Tolerance: 10%; Vendor: DigiKey; Vendor Part#: 311-1020-1-ND; eI Part#: 03_00019_01
C24 = 11_C_0: CAP CER 470PF 50V 5% NP0 0402; Manufacture Part Number: C1005C0G1H471JT000F; Mfg: Murata; Mfg Part#: GRM1555C1H471JA01D; Mounting Status: NU; Mounting_Status: NU; Oper. Temp. Range: -55C to 125C; Package: 0402; ProcessType: SMT; RoHS: Yes; Tolerance: 5%; Vendor: DigiKey; Vendor Part#: 490-1297-1-ND; eI Part#: 03_00218_05
C140 C143 C148 C151 C1148 C1149 = 11_C_0: CAP 10nF 16V CERAMIC 0402 SMD; Alt Mfg: Murata; Alt Mfg Part#: GRM155R71C103KA01D; Manufacture Part Number: C1005X7R1C103K||2238 787 15636||CC0402KRX7R7BB103; Mfg: Panasonic - ECG; Mfg Part#: ECJ-0EB1C103K; Oper. Temp. Range: -55C to 125C; Package: 0402; ProcessType: SMT; RoHS: Yes; Tolerance: 10%; Vendor: DigiKey; Vendor Part#: PCC103BQCT-ND; eI Part#: 03_00025_01
C142 C145 C150 = 11_C_0: CAP CER 4.7UF 10V Y5V 0603; Manufacture Part Number: GRM188R60J475K||C1608X5R0J475KT; Mfg: Murata; Mfg Part#: GRM188F51A475ZE20D; Oper. Temp. Range: -55C to 85C; Package: 0603; ProcessType: SMT; RoHS: Yes; Tolerance: 10%; Vendor: DigiKey; Vendor Part#: 490-3302-1-ND; eI Part#: 03_00276_01
LAN1 = 1652_RJ45_17P_101112FHBMAM_0: CONN RJ45 100/1000 1x1Integrated magnetics; Alt Mfg: Suyin; Alt Mfg Part#: 101112FHBMAM404ZA; Characteristic: <Characteristic>; Manufacture Part Number: 101112FHBMAM404ZA; Mfg: Pulse; Oper. Temp. Range: --NA--; Package: RJ45+XFMR+LED; ProcessType: DIP; RoHS: Yes; Tolerance: --NA--; Vendor: --NA--; Vendor Part#: --NA--; eI Part#: 09_00017_01
PHY1 = 88E1112: IC 10/100/1000 Gigabit Ethernet Transceiver; Mfg: Marvell; Mfg Part#: 88E1112-xx-NNC1C000; Vendor: Marvell; Vendor Part#: 88E1112-xx-NNC1C000; eI Part#: 01_00846_01
R26-R29 R31-R34 = 10_R_0: RES 49.9 OHM 1/10W 1% 0402 SMD; Alt Mfg: Yageo; Alt Mfg Part#: RC0402FR-0749R9L; Manufacture Part Number: 0402WGF499JTCE||232270674999L||RC0402FR-0749R9||RM04FTN49R9; Mfg: Panasonic - ECG; Mfg Part#: ERJ-2RKF49R9X; Oper. Temp. Range: -55C to 125C; Package: 0402; ProcessType: SMT; RoHS: Yes; Tolerance: 1%; Vendor: DigiKey; Vendor Part#: P49.9LCT-ND; eI Part#: 02_00025_01
R147 R391 R392 = 10_R_0: RES 4.99K OHM 1/10W 1% 0402 SMD; Manufacture Part Number: 0402WGF4991TCE||RM04FTN4991; Mfg: Panasonic - ECG; Mfg Part#: ERJ-2RKF4991X; Oper. Temp. Range: -55C to 125C; Package: 0402; ProcessType: SMT; Remark: Alt part is 1/16W; RoHS: Yes; Tolerance: 1%; Vendor: DigiKey; Vendor Part#: P4.99KLCT-ND; eI Part#: 02_00038_01
R431 = 10_R_0: RES 1.00M OHM 1/16W 1% 0402 SMD; Manufacture Part Number: 0402WGF4991TCE||RM04FTN4991; Mfg: Yageo; Mfg Part#: RC0402FR-071ML; Mounting Status: NU; Mounting_Status: NU; Oper. Temp. Range: -55C to 125C; Package: 0402; ProcessType: SMT; Remark: Alt part is 1/16W; RoHS: Yes; Tolerance: 1%; Vendor: DigiKey; Vendor Part#: 311-1.00MLRCT-ND; eI Part#: 02_00057_02
R774-R779 = 10_R_0: RES ZERO OHM 1/10W 5% 0402 SMD; Alt Mfg: Yageo; Alt Mfg Part#: RC0402JR-070RL; Manufacture Part Number: 0402WGJ0000TCE||RC0402JR-070RL||RM04JTN0; Mfg: Panasonic - ECG; Mfg Part#: ERJ-2GE0R00X; Oper. Temp. Range: -55C to 125C; Package: 0402; ProcessType: SMT; Remark: Alt part is 1/16W; RoHS: Yes; Tolerance: 5%; Vendor: DigiKey; Vendor Part#: P0.0JCT-ND; eI Part#: 02_00019_01
R1273 = 10_R_0: RES 4.7K OHM 1/10W 5% 0402 SMD; Alt Mfg: Yageo; Alt Mfg Part#: RC0402JR-074K7L; Mfg: Panasonic - ECG; Mfg Part#: ERJ-2GEJ472X; Oper. Temp. Range: -55C ~ 125C; Package: 0402; ProcessType: SMT; Remark: Alt part is 1/16W; RoHS: Yes; Tolerance: 1%; Vendor: DigiKey; Vendor Part#: P4.7KJCT-ND; eI Part#: 02_00023_01
R1656-R1658 = 10_R_0: RES 4.7K OHM 1/10W 5% 0402 SMD; Alt Mfg: Yageo; Alt Mfg Part#: RC0402JR-074K7L; Manufacture Part Number: 0402WGF392JTCE||RM04FTN39R2; Mfg: Panasonic - ECG; Mfg Part#: ERJ-2GEJ472X; Oper. Temp. Range: -55C to 125C; Package: 0402; ProcessType: SMT; Remark: Alt part is 1/16W; RoHS: Yes; Tolerance: 1%; Vendor: DigiKey; Vendor Part#: P4.7KJCT-ND; eI Part#: 02_00023_01
U252 = 14S_TI_SN74LVC1G07_SOT-23-5: IC BUFF/DVR NON-INVERT SOT235; Mfg: Texas Instruments; Oper. Temp. Range: -40°C ~ 85°C; Package: SOT-23-5; ProcessType: SMT; RoHS: Yes; Vendor: DigiKey; Vendor Part#: 296-8485-1-ND; eI Part#: 01_00844_01
U264 = AT24C02A: IC EEPROM 2KBIT 400KHZ 8TSSOP; Mfg: Microchip Technology; Oper. Temp. Range: -40°C ~ 85°C; Package: 8-TSSOP; RoHS: Yes; Vendor: DigiKey; Vendor Part#: 24LC02B-I/ST-ND; eI Part#: 01_00853_01
Y3 = CRYSTAL-4_PIN: CRYSTAL 25.000MHZ 18PF FUND SMD; Mfg: Abracon Corporation; Oper. Temp. Range: -20C to 60C; Package: 5.0mm x 3.2mm; RoHS: Yes; Specifications: CRYSTAL 25.000MHZ 18PF FUND SMD; Vendor: DigiKey; Vendor Part#: 535-9128-1-ND; eI Part#: 08_00006_01
DSP1 = TMS320C6657: TI DSP, Dual C66x™ DSP Cores; Mfg: Texas Instruments; RoHS: Yes; Vendor: Texas Instruments; eI Part#: 01_00878_01
BRK1 = 00_SOCKET841_CSBGA841: DSP SOCKET 625P; Mfg: Contech Solutions Inc.; Mfg Part#: CSBGA625-0.8-RCS-SNT1; Mounting Status: NU; Mounting_Status: NU; ProcessType: DIP; RoHS: Yes; Vendor: Contech Solutions Inc.; Vendor Part#: CSBGA625-0.8-RCS-SNT1; eI Part#: -- NA --
DM1 = DUMMY_0: Universal Desktop Power Brick Adapter, 30W; Mfg: KingWall; Mfg Part#: AS300-120-AQ250-E0902; RoHS: Yes; Specifications: Universal Power Adapter, 30W; Vendor: KingWall Electronics; Vendor Part#: AS300-120-AQ250-E0902; eI Part#: -- NA --
DM2 = DUMMY_0: Cable Ethernet - CAT6, ~ 2 meter length; Mfg: Li Fa Shun; Mfg Part#: -- NA --; RoHS: Yes; Specifications: Cable Ethernet - CAT6, ~ 2 meter length; Vendor: Li Fa Shun; Vendor Part#: -- NA --; eI Part#: -- NA --
DM3 = DUMMY_0: Heat-Sink, Clip type, MBA21002-20P/3.4Y+T710; Mfg: MALICO INC; Mfg Part#: CMBA0221212001-00; RoHS: Yes; Specifications: Heat-Sink, Clip type, for 23x23 mm chipset; Vendor: Malico Inc; Vendor Part#: CMBA0221212001-00; eI Part#: -- NA --
DM4 = DUMMY_0: UART 3-Pin to DCE-9 Pin Cable; Mfg: Li Fa Shun; Mfg Part#: -- NA --; RoHS: Yes; Specifications: UART 3-Pin to DCE-9 Pin Cable; Vendor: Li Fa Shun; Vendor Part#: -- NA --; eI Part#: -- NA --
DM5 = DUMMY_0: Cable USB Type A to Mini B, ~ 1 meter length; Mfg: Li Fa Shun; Mfg Part#: -- NA --; RoHS: Yes; Specifications: Cable USB Type A to Mini B, ~ 1 meter length; Vendor: Li Fa Shun; Vendor Part#: -- NA --; eI Part#: -- NA --
DM6-DM9 = DUMMY_0: Screw 3mm, Length 8mm, Head 5.2mm; RoHS: Yes; Specifications: Screw 3mm, Length 8mm, Head 5.2mm
DM10-DM13 = DUMMY_0: Stud  5.5mm o.d. x 3mm i.d. x12mm Height; Mfg: -- NA --; Mfg Part#: -- NA --; Package: -- NA --; RoHS: Yes; Specifications: Stud  5.5mm o.d. x 3mm i.d. x12mm Height; Vendor: -- NA --; Vendor Part#: -- NA --; eI Part#: -- NA --
DM14 = DUMMY_0: Universal Travel Adaptor, 250V/10A 75 x 50 x 40 mm; Mfg: Jinggoal Int.; Mfg Part#: JC261; RoHS: Yes; Vendor: Jinggoal Int.; Vendor Part#: JC261; eI Part#: -- NA --
DM15 = DUMMY_0: US Style AC Mains Cable, Match with Power Brick Adapter; RoHS: Yes
DM16-DM19 = DUMMY_0: CONN JUMPER SHORTING TIN; Mfg: Sullins Connector Solutions; Mfg Part#: STC02SYAN; RoHS: Yes; Specifications: CONN JUMPER SHORTING TIN; Vendor: DigiKey; Vendor Part#: S9000-ND
FM1-FM4 = 00_Fiducial_0: Fiducial Mark; Mfg: -- NA --; Mfg Part#: -- NA --; ProcessType: SMT; RoHS: Yes; Vendor: -- NA --; Vendor Part#: -- NA --; eI Part#: -- NA --
H1-H4 = 00_SCREWHOLE_CIRCLE_NPTH_1: SCREW HOLE  C3.5 D3.5 NPTH; Advansus Part Number: 0020200013; Avalue Part Number: 0020200013; Part Number: 0020200013; ProcessType: SMT
H5 = 00_H27P35-MTH_0: SCREW HOLE  C3.5 D2.7 PTH; Mfg: -- NA --; Mfg Part#: -- NA --; ProcessType: SMT; RoHS: Yes; Vendor: -- NA --; Vendor Part#: -- NA --; eI Part#: -- NA --

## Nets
AVCC2V5: B7.1 C140.1 C141.1 C142.1 C1146.1 C1147.1 C1148.1 C1149.1 PHY1.6(VDDAL_1) PHY1.7(VDDAH_1) PHY1.13(VDDAL_2) PHY1.14(VDDAH_2) PHY1.20(VDDA_1) PHY1.23(VDDA_2) PHY1.24(VDDA_3) PHY1.29(VDDA_4) PHY1.33(VDDA_5)
GND: B3.1 B11.2(GND) B12.2(GND) B13.2(GND) B14.2(GND) B15.2(GND) C21.1 C22.1 C23.1 C24.1 C25.1 C29.2 C30.2 C50.2 C57.2 C58.2 C61.2 C62.2 C140.2 C141.2 C142.2 C143.2 C144.2 C145.2 C148.2 C149.2 C150.2 C151.2 C152.2 C158.2 C159.2 C309.1 C310.1 C311.1 C312.1 C313.1 C314.1 C315.1 C316.1 C317.1 C318.1 C319.1 C320.2 C321.1 C322.2 C323.1 C324.2 C329.1 C330.2 C331.1 C332.2 C333.1 C334.1 C335.1 C336.2 C366.1 C519.2 C1146.2 C1147.2 C1148.2 C1149.2 C1372.2 C1526.2 C1527.2 C1528.2 CLK2.36(GND_VCO) CLK2.49(EPAD) EMU1.A2 EMU1.A3 EMU1.A4 EMU1.A5 EMU1.A6 EMU1.A7 EMU1.A9 EMU1.A10 EMU1.A11 EMU1.A12 EMU1.A13 EMU1.A14 EMU1.B1 EMU1.B15 EMU1.C1 EMU1.C15 EMU1.D2 EMU1.D3 EMU1.D4 EMU1.D5 EMU1.D6 EMU1.D7 EMU1.D8 EMU1.D9 EMU1.D10 EMU1.D11 EMU1.D12 EMU1.D13 EMU1.D14 EMU1.D15 NAND1.C5(VSS1) NAND1.K3(VSS2) NAND1.K8(VSS3) PHY1.55(VSS_1) PHY1.63(VSS_2) PHY1.65(ePAD) R67.2 R135.1 R147.2 R172.2 R366.1 R391.2 R392.2 R776.1 R779.1 R904.2 R905.2 R1273.2 R2226.1 U252.3 U264.1(A0) U264.2(A1) U264.3(A2) U264.4(VSS) U268.2(B) U268.3(GND) U269.2(B) U269.3(GND) Y3.2 Y3.4 Y5.2 ; also on sheet 4 5 6 7 8 9 12 13 14 15 23 26 27 28 29
GND_LAN: B3.2 LAN1.H3(PTH_1) LAN1.H4(PTH_2)
VCC1V2: C148.1 C149.1 C150.1 C151.1 C152.1 PHY1.39(DVDD_1) PHY1.43(DVDD_2) PHY1.47(DVDD_3) PHY1.62(DVDD_4) PHY1.64(DVDD_5) ; also on sheet 15 29
VCC1V8: C158.1 C159.1 C519.1 C1526.1 C1527.1 NAND1.H8(VCC2) NAND1.J6(VCC1) R134.1 R183.1 R290.1 R658.1 R893.1 R895.1 R896.1 R897.1 R901.1 R902.1 R1119.1 U268.5(VCC) U269.5(VCC) ; also on sheet 4 5 6 9 12 13 15 28
VCC2V5: B7.2 B37.1 C62.1 C143.1 C144.1 C145.1 C1372.1 LAN1.14 LAN1.16 PHY1.37(VDDO_1) PHY1.56(VDDO_2) R99.2 R146.1 R431.2 R764.1 R765.1 R1656.2 R1657.2 R1658.1 R2203.2 U252.5 U264.8(VCC) ; also on sheet 13 15
VCC3V3_AUX: B11.1(IN) B12.1(IN) B13.1(IN) B14.1(IN) B15.1(IN) C309.2 C310.2 C311.2 C312.2 C313.2 C314.2 C315.2 C316.2 C317.2 C318.2 C319.2 CLK2.1(VCC_IN_SEC) CLK2.8(VCC_OUT1) CLK2.11(VCC_OUT2) CLK2.15(VCC_AUXOUT) CLK2.18(VCC_OUT3) CLK2.21(VCC_OUT4) CLK2.26(VCC_OUT5) CLK2.29(VCC_OUT6) CLK2.32(VCC_OUT7) CLK2.44(VCC_AUXIN) CLK2.47(VCC_IN_PRI) R170.2 R173.2 R903.1 ; also on sheet 4 6 12 13 14 15 23 26 27 28 29
VCC_VCO2A: B11.3(OUT) C321.2 C322.1 CLK2.34(VCC_VCO1)
VCC_VCO2B: B13.3(OUT) C329.2 C330.1 CLK2.35(VCC_VCO2)
VCCPLLA2A: B15.3(OUT) C335.2 C336.1 CLK2.5(VCC1_PLL1)
VCCPLLA2B: B14.3(OUT) C331.2 C332.1 CLK2.39(VCC1_PLL2)
VCCPLLA2C: B12.3(OUT) C323.2 C324.1 CLK2.42(VCC1_PLL3)
AMC_SGMII_RXN: C1370.2 ; also on sheet 12
AMC_SGMII_RXN_C: C1370.1 PHY1.15(FIN_N)
AMC_SGMII_RXP: C353.2 ; also on sheet 12
AMC_SGMII_RXP_C: C353.1 PHY1.16(FIN_P)
AMC_SGMII_TXN: PHY1.10(FOUT_N) ; also on sheet 12
AMC_SGMII_TXP: PHY1.11(FOUT_P) ; also on sheet 12
CLOCK2_PLL_LOCK: CLK2.37(PLL_LOCK) ; also on sheet 26
CLOCK2_SSPCK: CLK2.24(SPI_CLK) ; also on sheet 26
CLOCK2_SSPCS1: CLK2.25(SPI_LE) ; also on sheet 26
CLOCK2_SSPSI: CLK2.23(SPI_MOSI) ; also on sheet 26
CLOCK2_SSPSO: CLK2.22(SPI_MISO) ; also on sheet 26
CORECLKN: CLK2.10(U3N) ; also on sheet 28
CORECLKP: CLK2.9(U3P) ; also on sheet 28
DDRCLKN: CLK2.17(U2N) ; also on sheet 28
DDRCLKP: CLK2.16(U2P) ; also on sheet 28
DSP_EMIFA00: DSP1.K1(UPP_XD0/EMIFA00) ; also on sheet 23
DSP_EMIFA01: DSP1.M3(UPP_XD1/EMIFA01) ; also on sheet 23
DSP_EMIFA02: DSP1.L2(UPP_XD2/EMIFA02) ; also on sheet 23
DSP_EMIFA03: DSP1.P5(UPP_XD3/EMIFA03) ; also on sheet 23
DSP_EMIFA04: DSP1.L1(UPP_XD4/EMIFA04) ; also on sheet 23
DSP_EMIFA05: DSP1.P4(UPP_XD5/EMIFA05) ; also on sheet 23
DSP_EMIFA06: DSP1.M2(UPP_XD6/EMIFA06) ; also on sheet 23
DSP_EMIFA07: DSP1.M1(UPP_XD7/EMIFA07) ; also on sheet 23
DSP_EMIFA08: DSP1.N2(UPP_XD8/EMIFA08) ; also on sheet 23
DSP_EMIFA09: DSP1.P3(UPP_XD9/EMIFA09) ; also on sheet 23
DSP_EMIFA10: DSP1.N1(UPP_XD10/EMIFA10) ; also on sheet 23
DSP_EMIFA11: DSP1.P2(UPP_XD11/EMIFA11) NAND1.C4(ALE) ; also on sheet 23
DSP_EMIFA12: DSP1.P1(UPP_XD12/EMIFA12) NAND1.D5(CLE) ; also on sheet 23
DSP_EMIFA13: DSP1.R5(UPP_XD13/EMIFA13) ; also on sheet 23
DSP_EMIFA14: DSP1.R3(UPP_XD14/EMIFA14) ; also on sheet 23
DSP_EMIFA15: DSP1.R4(UPP_XD15/EMIFA15) ; also on sheet 23
DSP_EMIFA16: DSP1.R2(UPP_CH0_CLK/EMIFA16) ; also on sheet 23
DSP_EMIFA17: DSP1.R1(UPP_CH0_START/EMIFA17) ; also on sheet 23
DSP_EMIFA18: DSP1.T4(UPP_CH0_ENABLE/EMIFA18) ; also on sheet 23
DSP_EMIFA19: DSP1.T1(UPP_CH0_WAIT/EMIFA19) ; also on sheet 23
DSP_EMIFA20: DSP1.T5(UPP_CH1_CLK/EMIFA20) ; also on sheet 23
DSP_EMIFA21: DSP1.U1(UPP_CH1_START/EMIFA21) ; also on sheet 23
DSP_EMIFA22: DSP1.U2(UPP_CH1_ENABL/EMIFA22) ; also on sheet 23
DSP_EMIFA23: DSP1.U3(UPP_CH1_WAIT/EMIFA23) ; also on sheet 23
DSP_EMIFBE0Z: DSP1.J1(EMIFBE0z) ; also on sheet 23
DSP_EMIFBE1Z: DSP1.L3(EMIFBE1z) ; also on sheet 23
DSP_EMIFCE0Z: NAND1.C6(\\~{C}E) R236.1
DSP_EMIFCE1Z: R248.1 ; also on sheet 23
DSP_EMIFCE2Z: R249.1 ; also on sheet 23
DSP_EMIFD0: DSP1.U4(EMIFD00/UPP_D0) NAND1.H4(IO0) ; also on sheet 23
DSP_EMIFD1: DSP1.U5(EMIFD01/UPP_D1) NAND1.J4(IO1) ; also on sheet 23
DSP_EMIFD2: DSP1.V1(EMIFD02/UPP_D2) NAND1.K4(IO2) ; also on sheet 23
DSP_EMIFD3: DSP1.V2(EMIFD03/UPP_D3) NAND1.K5(IO3) ; also on sheet 23
DSP_EMIFD4: DSP1.V3(EMIFD04/UPP_D4) NAND1.K6(IO4) ; also on sheet 23
DSP_EMIFD5: DSP1.V4(EMIFD05/UPP_D5) NAND1.J7(IO5) ; also on sheet 23
DSP_EMIFD6: DSP1.W1(EMIFD06/UPP_D6) NAND1.K7(IO6) ; also on sheet 23
DSP_EMIFD7: DSP1.V5(EMIFD07/UPP_D7) NAND1.J8(IO7) ; also on sheet 23
DSP_EMIFD8: DSP1.W2(EMIFD08/UPP_D8) ; also on sheet 23
DSP_EMIFD9: DSP1.Y1(EMIFD09/UPP_D9) ; also on sheet 23
DSP_EMIFD10: DSP1.W4(EMIFD10/UPP_D10) ; also on sheet 23
DSP_EMIFD11: DSP1.Y2(EMIFD11/UPP_D11) ; also on sheet 23
DSP_EMIFD12: DSP1.W5(EMIFD12/UPP_D12) ; also on sheet 23
DSP_EMIFD13: DSP1.AA1(EMIFD13/UPP_D13) ; also on sheet 23
DSP_EMIFD14: DSP1.AB1(EMIFD14/UPP_D14) ; also on sheet 23
DSP_EMIFD15: DSP1.AA2(EMIFD15/UPP_D15) ; also on sheet 23
DSP_EMIFOEZ: DSP1.L4(EMIFOEz) NAND1.D4(\\~{R}E) ; also on sheet 23
DSP_EMIFRNW: DSP1.L5(EMIFRnW) ; also on sheet 23
DSP_EMIFWAIT0: DSP1.N5(EMIFWAIT0) NAND1.C8(R~{/B}) R134.2
DSP_EMIFWAIT1: DSP1.M4(EMIFWAIT1/UPP_2XTXCLK) R183.2 ; also on sheet 23
DSP_EMIFWEZ: DSP1.K4(EMIFWEz) NAND1.C7(\\~{W}E) ; also on sheet 23
DSP_EMU_00: DSP1.V24(EMU00) ; also on sheet 6
DSP_EMU_01: DSP1.V25(EMU01) ; also on sheet 6
DSP_EMU_02: DSP1.W25(EMU02) R266.1
DSP_EMU_03: DSP1.W23(EMU03) R267.2
DSP_EMU_04: DSP1.W24(EMU04) R269.2
DSP_EMU_05: DSP1.Y25(EMU05) R268.1
DSP_EMU_06: DSP1.Y24(EMU06) R273.2
DSP_EMU_07: DSP1.Y23(EMU07) R270.1
DSP_EMU_08: DSP1.W22(EMU08) R272.2
DSP_EMU_09: DSP1.Y22(EMU09) R271.1
DSP_EMU_10: DSP1.AA24(EMU10) R281.2
DSP_EMU_11: DSP1.AA25(EMU11) R274.2
DSP_EMU_12: DSP1.AB25(EMU12) R276.1
DSP_EMU_13: DSP1.AC25(EMU13) R275.2
DSP_EMU_14: DSP1.AA23(EMU14) R280.1
DSP_EMU_15: DSP1.AB22(EMU15) R277.2
DSP_EMU_16: DSP1.AD25(EMU16) R278.2
DSP_EMU_17: DSP1.AC24(EMU17) R279.1
DSP_EMU_18: DSP1.Y21(EMU18) R282.2
DSP_SGMII_RXN: PHY1.1(SOUT_N) ; also on sheet 13
DSP_SGMII_RXP: PHY1.2(SOUT_P) ; also on sheet 13
DSP_SGMII_TXN: C136.2 ; also on sheet 13
DSP_SGMII_TXN_C: C136.1 PHY1.8(SIN_N)
DSP_SGMII_TXP: C137.2 ; also on sheet 13
DSP_SGMII_TXP_C: C137.1 PHY1.9(SIN_P)
DSP_TCK: DSP1.AD17(TCK) ; also on sheet 6
DSP_TDI: DSP1.AE17(TDI) ; also on sheet 6
DSP_TDO: DSP1.AD19(TDO) ; also on sheet 6
DSP_TMS: DSP1.AE18(TMS) ; also on sheet 6
DSP_TRST#: DSP1.AB19(TRSTz) ; also on sheet 6
EMU_00_R: EMU1.B14 R287.2 R901.2
EMU_01_R: EMU1.C14 R286.1 R902.2
EMU_EMU_00: R287.1 ; also on sheet 6
EMU_EMU_01: R286.2 ; also on sheet 6
EMU_RTCK: EMU1.C8 R377.2
EMU_TCK: R292.1 R1119.2 R1120.2 U268.1(A) U269.1(A)
EMU_TCK_BUF: R378.2 ; also on sheet 6
EMU_TCK_R: C555.1 EMU1.B12 R292.2 R896.2
EMU_TDI: R294.1 ; also on sheet 6
EMU_TDI_R: EMU1.B4 R294.2 R895.2
EMU_TDO: R293.1 ; also on sheet 6
EMU_TDO_R: EMU1.B7 R293.2 R897.2
EMU_TMS: R295.1 ; also on sheet 6
EMU_TMS_R: EMU1.B2 R295.2 R893.2
EMU_TRST#: R288.2 ; also on sheet 6
EMU_TRST#_R: EMU1.C3 R288.1 R905.1
ETH_CONFIG0: PHY1.48(CONFIG[0]) R779.2
ETH_CONFIG1: PHY1.46(CONFIG[1]) R774.2
ETH_CONFIG2: PHY1.45(CONFIG[2]) R775.2
ETH_CONFIG3: PHY1.44(CONFIG[3]) R776.2
ETH_CONFIG4: PHY1.42(CONFIG[4]) R777.2
ETH_CONFIG5: PHY1.41(CONFIG[5]) R778.2
ETH_LOS/LED: PHY1.59(LOS) R1130.1 R1658.2
ETH_MDC: PHY1.57(MDC) ; also on sheet 13
ETH_MDIO: PHY1.58(MDIO) ; also on sheet 13
ETH_SCL: PHY1.54(SCL) R1657.1 U264.6(SCL)
ETH_SDA: PHY1.53(SDA) R1656.1 U264.5(SDA)
ETH_WP: R2203.1 R2226.2 U264.7(WP)
EXT_EMU_DET0: EMU1.A1 R903.2 ; also on sheet 6
HyperLink_CLKN: CLK2.28(U0N) ; also on sheet 28
HyperLink_CLKP: CLK2.27(U0P) ; also on sheet 28
LAN_RST: PHY1.52(RESET) R99.1 U252.4(OUT)
MDI0_N: LAN1.10(TD1-) PHY1.18(MDI[0]_P) R27.2
MDI0_P: LAN1.11(TD1+) PHY1.19(MDI[0]_N) R26.2
MDI1_N: LAN1.5(TD2-) PHY1.21(MDI[1]_P) R29.2
MDI1_P: LAN1.4(TD2+) PHY1.22(MDI[1]_N) R28.2
MDI2_N: LAN1.2(TD3-) PHY1.27(MDI[2]_P) R33.1
MDI2_P: LAN1.3(TD3+) PHY1.28(MDI[2]_N) R34.1
MDI3_N: LAN1.9(TD4-) PHY1.30(MDI[3]_P) R31.1
MDI3_P: LAN1.8(TD4+) PHY1.31(MDI[3]_N) R32.1
NAND_WP#: NAND1.C3(\\~{W}P) R135.2 ; also on sheet 29
P1_TCT: B37.2 C50.1 C57.1 C58.1 C61.1 LAN1.1(TCT3) LAN1.6(TCT2) LAN1.7(TCT4) LAN1.12(TCT1)
PCIECLKN: CLK2.7(U4N) ; also on sheet 28
PCIECLKP: CLK2.6(U4P) ; also on sheet 28
PHY_INT#: PHY1.61(INIT) R764.2 ; also on sheet 26
PHY_RST: U252.2(IN) ; also on sheet 26
REFCLK2_PD#: CLK2.12(Power_Down#) R366.2 ; also on sheet 26
REFCLK2_XTALIN: C366.2 CLK2.43(AUXIN) Y5.1
SRIOSGMIICLKN: CLK2.20(U1N) ; also on sheet 28
SRIOSGMIICLKP: CLK2.19(U1P) ; also on sheet 28
STATUS_0: PHY1.40(STATUS[0]) R35.1 R774.1 R778.1
STATUS_1: PHY1.38(STATUS[1]) R36.1 R775.1 R777.1
TCLKB_N: C598.2 C605.2 ; also on sheet 12
TCLKB_N_R: C598.1 ; also on sheet 29
TCLKB_P: C604.2 C606.2 ; also on sheet 12
TCLKB_P_R: C604.1 ; also on sheet 29
TRGRSTZ: EMU1.A15 R290.2 ; also on sheet 29
N59993765: DSP1.K5(EMIFCE0z) R236.2
N59993866: DSP1.G1(EMIFCE1z) R248.2
N59993968: DSP1.J2(EMIFCE2z) R249.2
N66897854: CLK2.13(AUXOUT) TP29.1
N66898237: CLK2.30(TESTOUTA) R172.1
N66898452: C320.1 CLK2.48(VBB)
N70130797: LAN1.17 R35.2
N70130812: C21.2 R26.1 R27.1
N70130816: C22.2 R28.1 R29.1
N70130826: LAN1.15 R36.2
N70130834: C30.1 R33.2 R34.2
N70130836: C29.1 R31.2 R32.2
N70130865: C24.2 LAN1.13 R1130.2
N70131176: PHY1.26(HSDAC_N) TP133.1
N70131254: PHY1.5(SCLK_P) R392.1
N70131352: PHY1.4(SCLK_N) R391.1
N70131441: PHY1.49(NORMAL) R765.2
N70131476: PHY1.34(TSTPT) TP162.1
N70131871: PHY1.25(HSDAC_P) TP23.1
N70132065: PHY1.17(RSET) R147.1
N70175349: EMU1.B5 R280.2
N70175364: EMU1.B8 R658.2
N70175388: EMU1.C4 R278.1
N70175445: EMU1.C9 R281.1
N70175460: EMU1.B3 R279.2
N70175537: EMU1.C13 R267.1
N70175572: EMU1.B13 R266.2
N70175615: EMU1.C2 R282.1
N70175718: EMU1.C7 R274.1
N70175813: EMU1.B11 R268.2
N70175835: EMU1.C12 R269.1
N70175959: EMU1.B10 R270.2
N70176063: EMU1.C6 R275.1
N70176163: EMU1.B9 R271.2
N70176178: EMU1.A8 R904.1
N70176180: EMU1.C11 R273.1
N70176296: EMU1.C5 R277.1
N70176352: EMU1.C10 R272.1
N70176369: EMU1.B6 R276.2
N70180183: C555.2 R67.1
N72320750: CLK2.31(REF_SEL) R170.1
N72358963: C334.2 CLK2.38(REG_CAP2)
N72358967: C333.2 CLK2.4(REG_CAP1)
N73137773: CLK2.33(TEST_MODE) R173.1
N73155196: C606.1 CLK2.45(PRIREF+)
N73157071: C605.1 CLK2.46(PRIREF-)
N74489699: C25.2 PHY1.36(XTAL1) R431.1 Y3.1
N74491435: C23.2 PHY1.35(XTAL2) Y3.3
N74678025: CLK2.3(SECREF+) TP37.1
N74679931: CLK2.2(SECREF-) TP36.1
N75429807: PHY1.50(PWRDN) R1273.1
N75729497: PHY1.60(SDET) R146.2
N79149279: CLK2.41(EXT_LFN) TP44.1
N79149311: CLK2.40(EXT_LFP) TP45.1
N81999132: R377.1 U268.4(Y)
N82000105: R378.1 U269.4(Y)
N82002027: C1528.1 R1120.1

Not connected (* = marked no-connect by the designer): CLK2 14(SYNC)*; DSP1 M5(EMIFCE3z)*; EMU1 D1* H1(PTH1)* H2(PTH2)*; FM1 1*; FM2 1*; FM3 1*; FM4 1*; H1 1(NPTH)*; H2 1(NPTH)*; H3 1(NPTH)*; H4 1(NPTH)*; H5 1*; LAN1 H1(NPTH_1)* H2(NPTH_2)*; NAND1 A1(DU1)* A2(DU2)* A9(DU3)* A10(DU4)* B1(DU5)* B9(DU6)* B10(DU7)* D3(NC26)* D6(NC1)* D7(NC2)* D8(NC3)* E3(NC4)* E4(NC5)* E5(NC6)* E6(NC7)* E7(NC8)* E8(NC9)* F3(NC10)* F4(NC11)* F5(NC12)* F6(NC13)* F7(NC27)* F8(NC14)* G3(NC18)* G4(NC25)* G5(NC28)* G6(NC15)* G7(NC16)* G8(NC17)* H3(NC19)* H5(NC20)* H6(NC21)* H7(NC22)* J3(NC23)* J5(NC24)* L1(DU8)* L2(DU9)* L9(DU10)* L10(DU11) M1(DU12)* M2(DU13)* M9(DU14)* M10(DU15)*; PHY1 3(S_VTT)* 12(F_VTT)* 32(NC)* 51(POL_RST)*; U252 1(NC)*

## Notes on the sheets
sheet 16
- NAND FLASH
- C6657 - EMIF
- C6657 - JTAG & EMU
- TI-60 Header
sheet 17
- TMDSEVM6657 - REVISION HISTORY
- PCB REV.
- SCH. REV.
- CHANGE DESCRIPTION
- DATE
- AUTHOR
- 0.6
- - CLK3 removed
  - Series Termination removed from GPIO0 to GPIO13 lines
- 3-FEB-2012
- eInfochips
- 1.0
- 1.1
- - D9 and D10 part changed with one with higher current capacity.
  - R134 changed to 1K from 4.7K
  - NU resistors R433 and R434 changed to 10K and 1.2K resp. They are to be mounted.
  - R12 and R17 replaced by 100nF caps C1225 and C1226
  - R70 and R71 mounting status changed from NU to populated.
  - U6 (DDR3 ECC chip) made NU.
  - DDR3 Clock frequency from Clock Gen changed to 50 MHz (software change only).
- 20-MAR-2012
- eInfochips
- 0.1
- - Clock buffer U1132 removed. 2 OR gates (U268, U269) and the corresponding circuitry to buffer EMU_TCK added.
  - 4 Test Points for Gnd added.
  - ETH_SCK net renamed to ETH_SDA
  - SIGDETunconnected with LOS; its directly pulled high. R145 and R146 removed
  - SYSPG_D1 LED changed to Yellow colour from Green
- 02-APR-2012
- eInfochips
- 2.0
- - 10 nF capacitors (C457 and C460) added on VCC12 input rail of U34.
  - Capacitors on CVDD rail optimized from two 220uF, two 100uF and four 47uF to two 100uF and two 47uF.
  - Capacitors on VCC1V0 rail optimized from one 220uF, three 47uF and one 10uF to two 47uF and one 10uF.
  - An additional 22uF cap (C549) added on VCC12 input for U29. C426 changed from 10nF to 100nF.
  - R183 changed to 1K from 4.7K.
  - SIGDET connected to VCC2V5 using R146.
  - R1273 changed to 4.7K from 10K.
- 02-MAY-2012
- eInfochips
- 0.2
- - L15 and L16 changed to 2.3uH and 1.2uH respectively
  - R251 and R373 changed to 22.1K
  - C549 moved before B158 on 12V plane
  - C2325 changed from 100nF to 10uF
  - R2203 made NU and R2226 to be mounted
- 0.3
- 07-MAY-2012
- eInfochips
- 0.4
- - NOR Flash density label corrected to 32 Mb from 16MB.
- 20-JUL-2012
- eInfochips
- 0.5
- - DISCLAIMER Changed
- 26-JUL-2012
- eInfochips
- - Asthetical Change
    Name swap between LVDS and HCSL on page 18
- 06-DEC-2012
- eInfochips
- 0.6
- 0.7
- - Asthetical Change
    Note for DDR3 Slew-Rate setting corrected on page 14
- 29-JAN-2013
- eInfochips
- 0.8
- - R82 and R83 changed to 10K
  - R85 and R957 made NU
- 22-FEB-2013
- eInfochips
- 0.9
- - The Resistors R896,R67 and capacitor C555 are redundant components on EMU_TCK and can be NU from design.
  - Pull-up resister R1119 on EMU_TCK change from 10K to 4.7K
- 28-NOV-2013
- eInfochips
- Dummy Components
- AMC Hole
- Mounting  Holes
- On Board Fiducials
sheet 18
- POWER CONSUMPTION
sheet 19
- ETHERNET PHY
- ETHERNET JACK
- LED (Colour)
- Link
- No Link
- LOS (Orange/Green)
- ON
- OFF
- If both fiber (SGMII) and copper (1000BASE-X) cables are
  connected, the preferred media will be selected based on
  value of register 16_2.11:10. If it is:
  00: Link with 1st media to establish link
  01: Prefer fiber media
  10: Prefer copper media
- 256 Bytes EEPROM
- Read Address: 1010 0001 (0x50)
  Write Address: 1010 0000 (0x50)
- LED (Colour)
- 1Gbps
- 100Mbps
- 10Mbps
- Activity
- No Activity
- Activity
- No Activity
- Activity
- No Activity
- Status 0 (Green)
- BLINK
- SOLID ON
- BLINK
- SOLID ON
- OFF
- OFF
- Status 1 (Orange)
- OFF
- OFF
- BLINK
- SOLID ON
- BLINK
- SOLID ON
- Pin to Configuration Bit Mapping
- PIN
- BIT[1]
- BIT[0]
- PIN
- VALUE
- POL_RST
- RESET=0
- RESET=1
- CONFIG0
- PHYADR[1]
- PHYADR[0]
- VDD0
- 11
- 0
- Reset
- Normal
- CONFIG1
- PHYADR[3]
- PHYADR[2]
- STATUS[0]
- 10
- 1 or
  Floating
- Normal
- Reset
- CONFIG2
- SGMII_CLK
- PHYADR[4]
- STATUS[1]
- 01
- CONFIG3
- SEL_TWSI
- SEL_VTT
- VSS
- 00
- CONFIG4
- EEPROM[1]
- EEPROM[0]
- FOR EMI
- CONFIG5
- MODE[1]
- MODE[0]
- PIN
- VALUE
- CONNECTION
- INTERPRETATION
- 01
- 01
- CONFIG0
- 00
- VSS
- PHY Address[1:0] is 00
- 10
- CONFIG1
- 10
- STATUS[0]
- PHY Address[3:2] is 10
- 10
- CONFIG2
- 01
- STATUS[1]
- SGMII_CLK not supplied; PHY Address[4] is 1
- 00
- CONFIG3
- 00
- VSS
- MDC/MDIO mode; S_VTT & F_VTT int supplied
- 00
- CONFIG4
- 01
- STATUS[1]
- Start reading from address 0
- CONFIG5
- 10
- STATUS[0]
- SGMII MAC Int to Auto Media select (Cu/SGMII)
sheet 20
- CLOCK GEN2
- These caps should be located
  near CDCE62005(CLK2)
- These caps should be located
  near CDCE62005(CLK2)
- 250.00MHz
- 250.00MHz
- 50.00MHz
- 100.00MHz
- 100.00MHz
sheet 21
- SCHEMATIC PAGE DESCRIPTION :
- 01 : COVER PAGE
  02 : TABLE OF CONTENTS
  03 : SYSTEM BLOCK DIAGRAM
  04 : PLACEMENT
  05 : POWER CONSUMPTION
  06 : POWER SEQUENCE
  07 : POWER DISTRIBUTION
  08 : CLOCK DIAGRAM
  09 : FPGA INTERFACE CONTROL
  10 : MANAGEMENT MAP
  11 : AMC CONNECTOR
  12 : MMC, HYPERLINK COMM
  13 : DSP - SERDES PORTS
  14 : DSP - DDR3
  15 : DDR3 & ECC
  16 : DSP - EMIF & JTAG
  17 : DSP - MISC
  18 : DSP - CLOCK & SMART REFLEX
  19 : CLOCK GENERATION
  20 : USB - JTAG
  21 : GIGABIT ETHERNET
  22 : FPGA - POWER, RESET CTRL, McBSP
  23 : FPGA - BOOT_MODE & SMART REFLEX
  24 : DSP - POWER 1
  25 : DSP - POWER 2
  26 : SMART REFLEX & CORE VOLT
  27 : POWER SUPPLY 1
  28 : POWER SUPPLY 2
  29 : REVISON HISTORY
sheet 22
- BLOCK DIAGRAM
